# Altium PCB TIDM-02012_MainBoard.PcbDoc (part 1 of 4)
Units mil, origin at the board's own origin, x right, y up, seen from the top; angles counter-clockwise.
Board outline 6550 x 5100 mil, 4 copper layers (Top Layer, Layer 1, Layer 2, Bottom Layer), stack 81.2 mil thick; 300 components, 157 nets, 916 pads, 350 vias.
Unrouted connection lines stored in the file: 93.
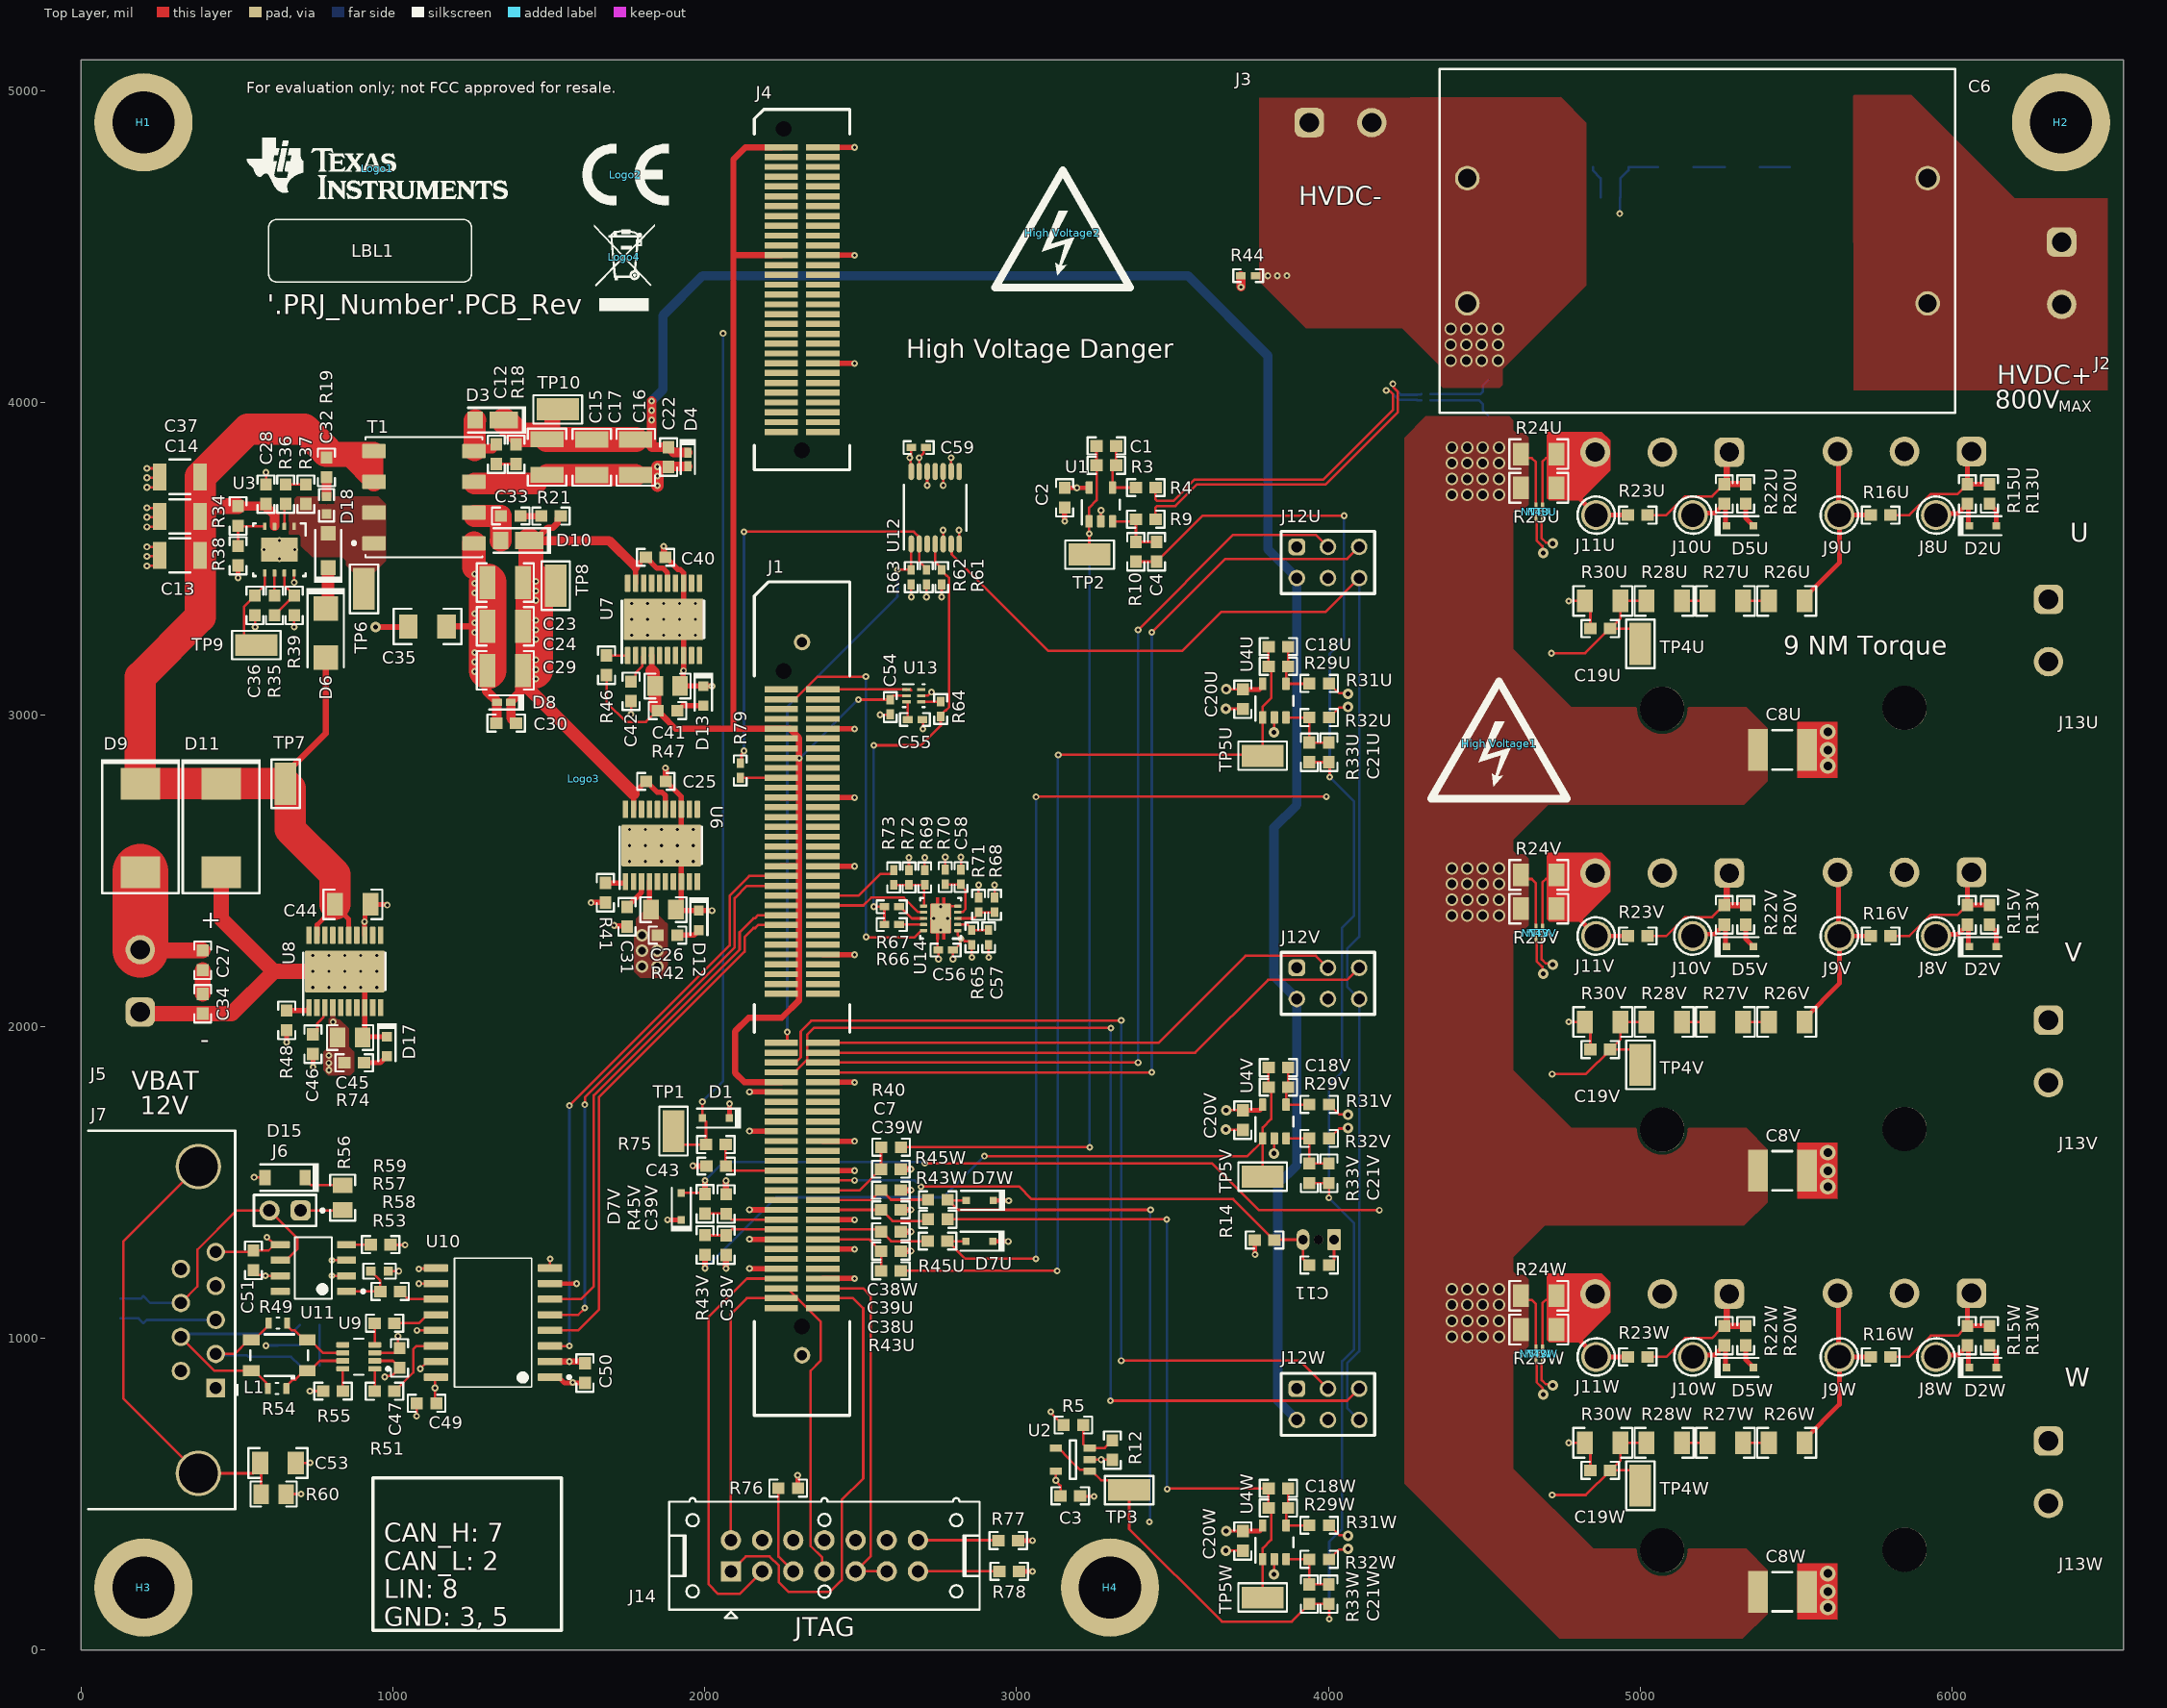
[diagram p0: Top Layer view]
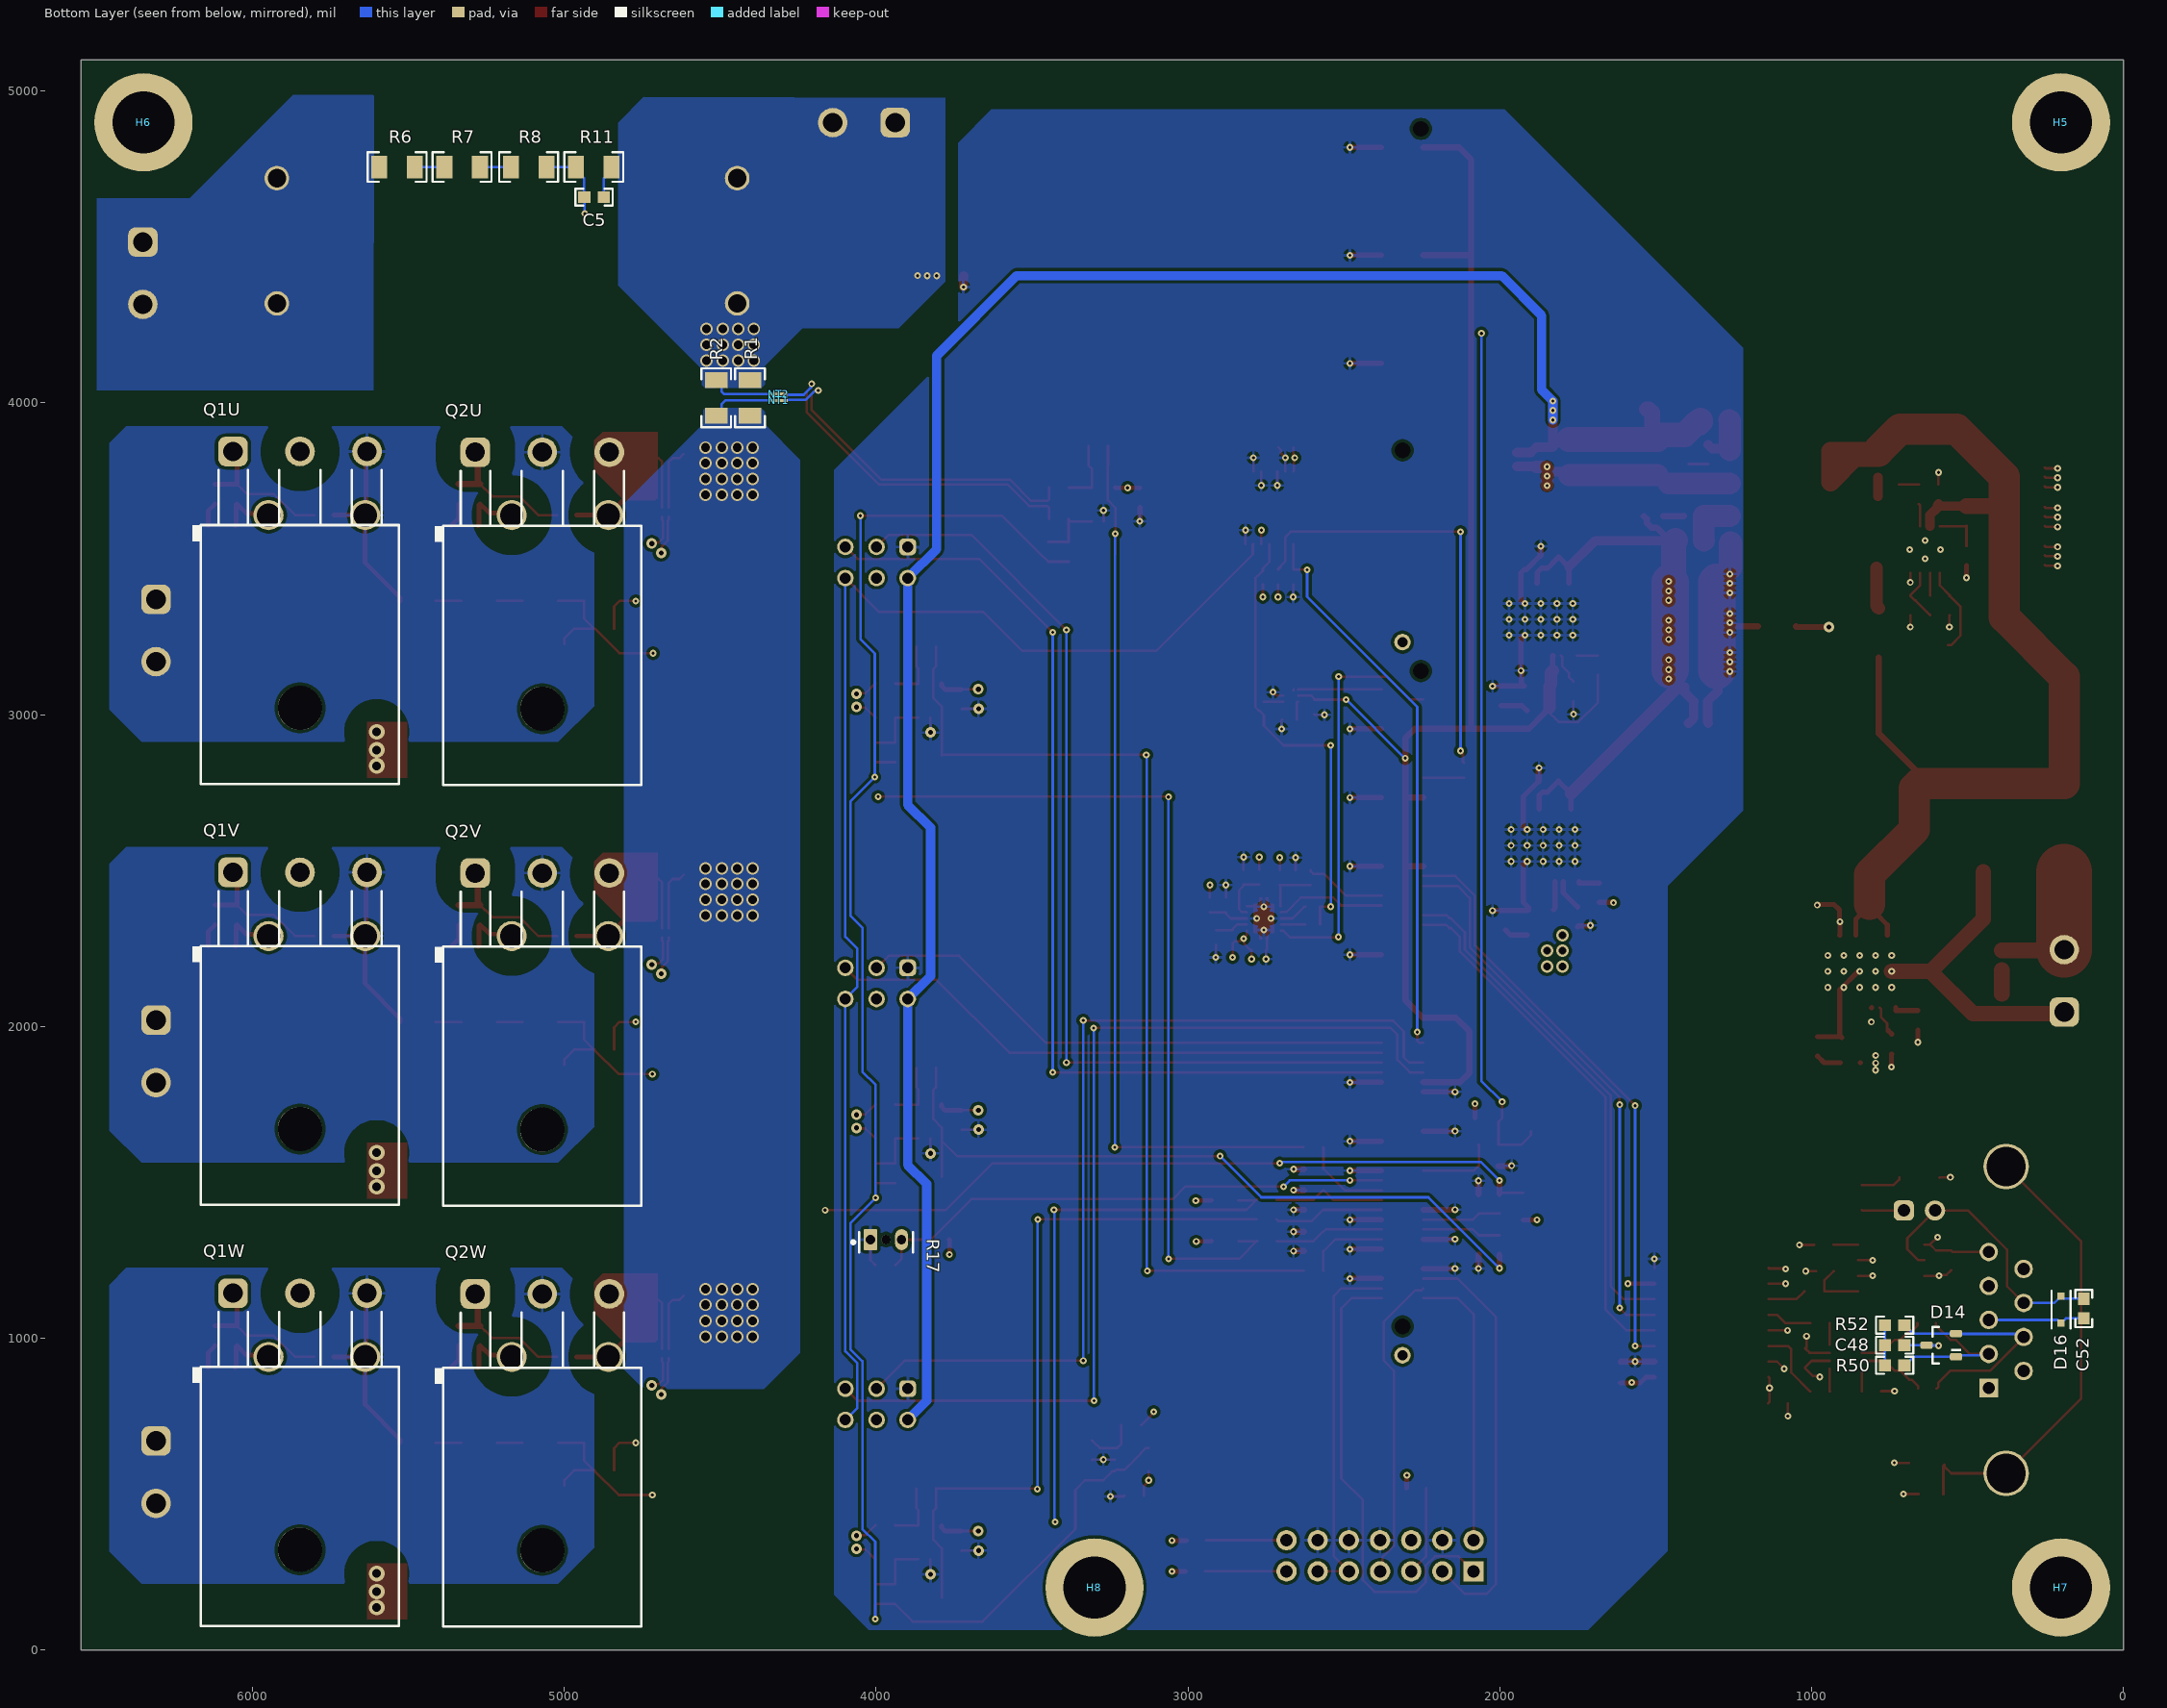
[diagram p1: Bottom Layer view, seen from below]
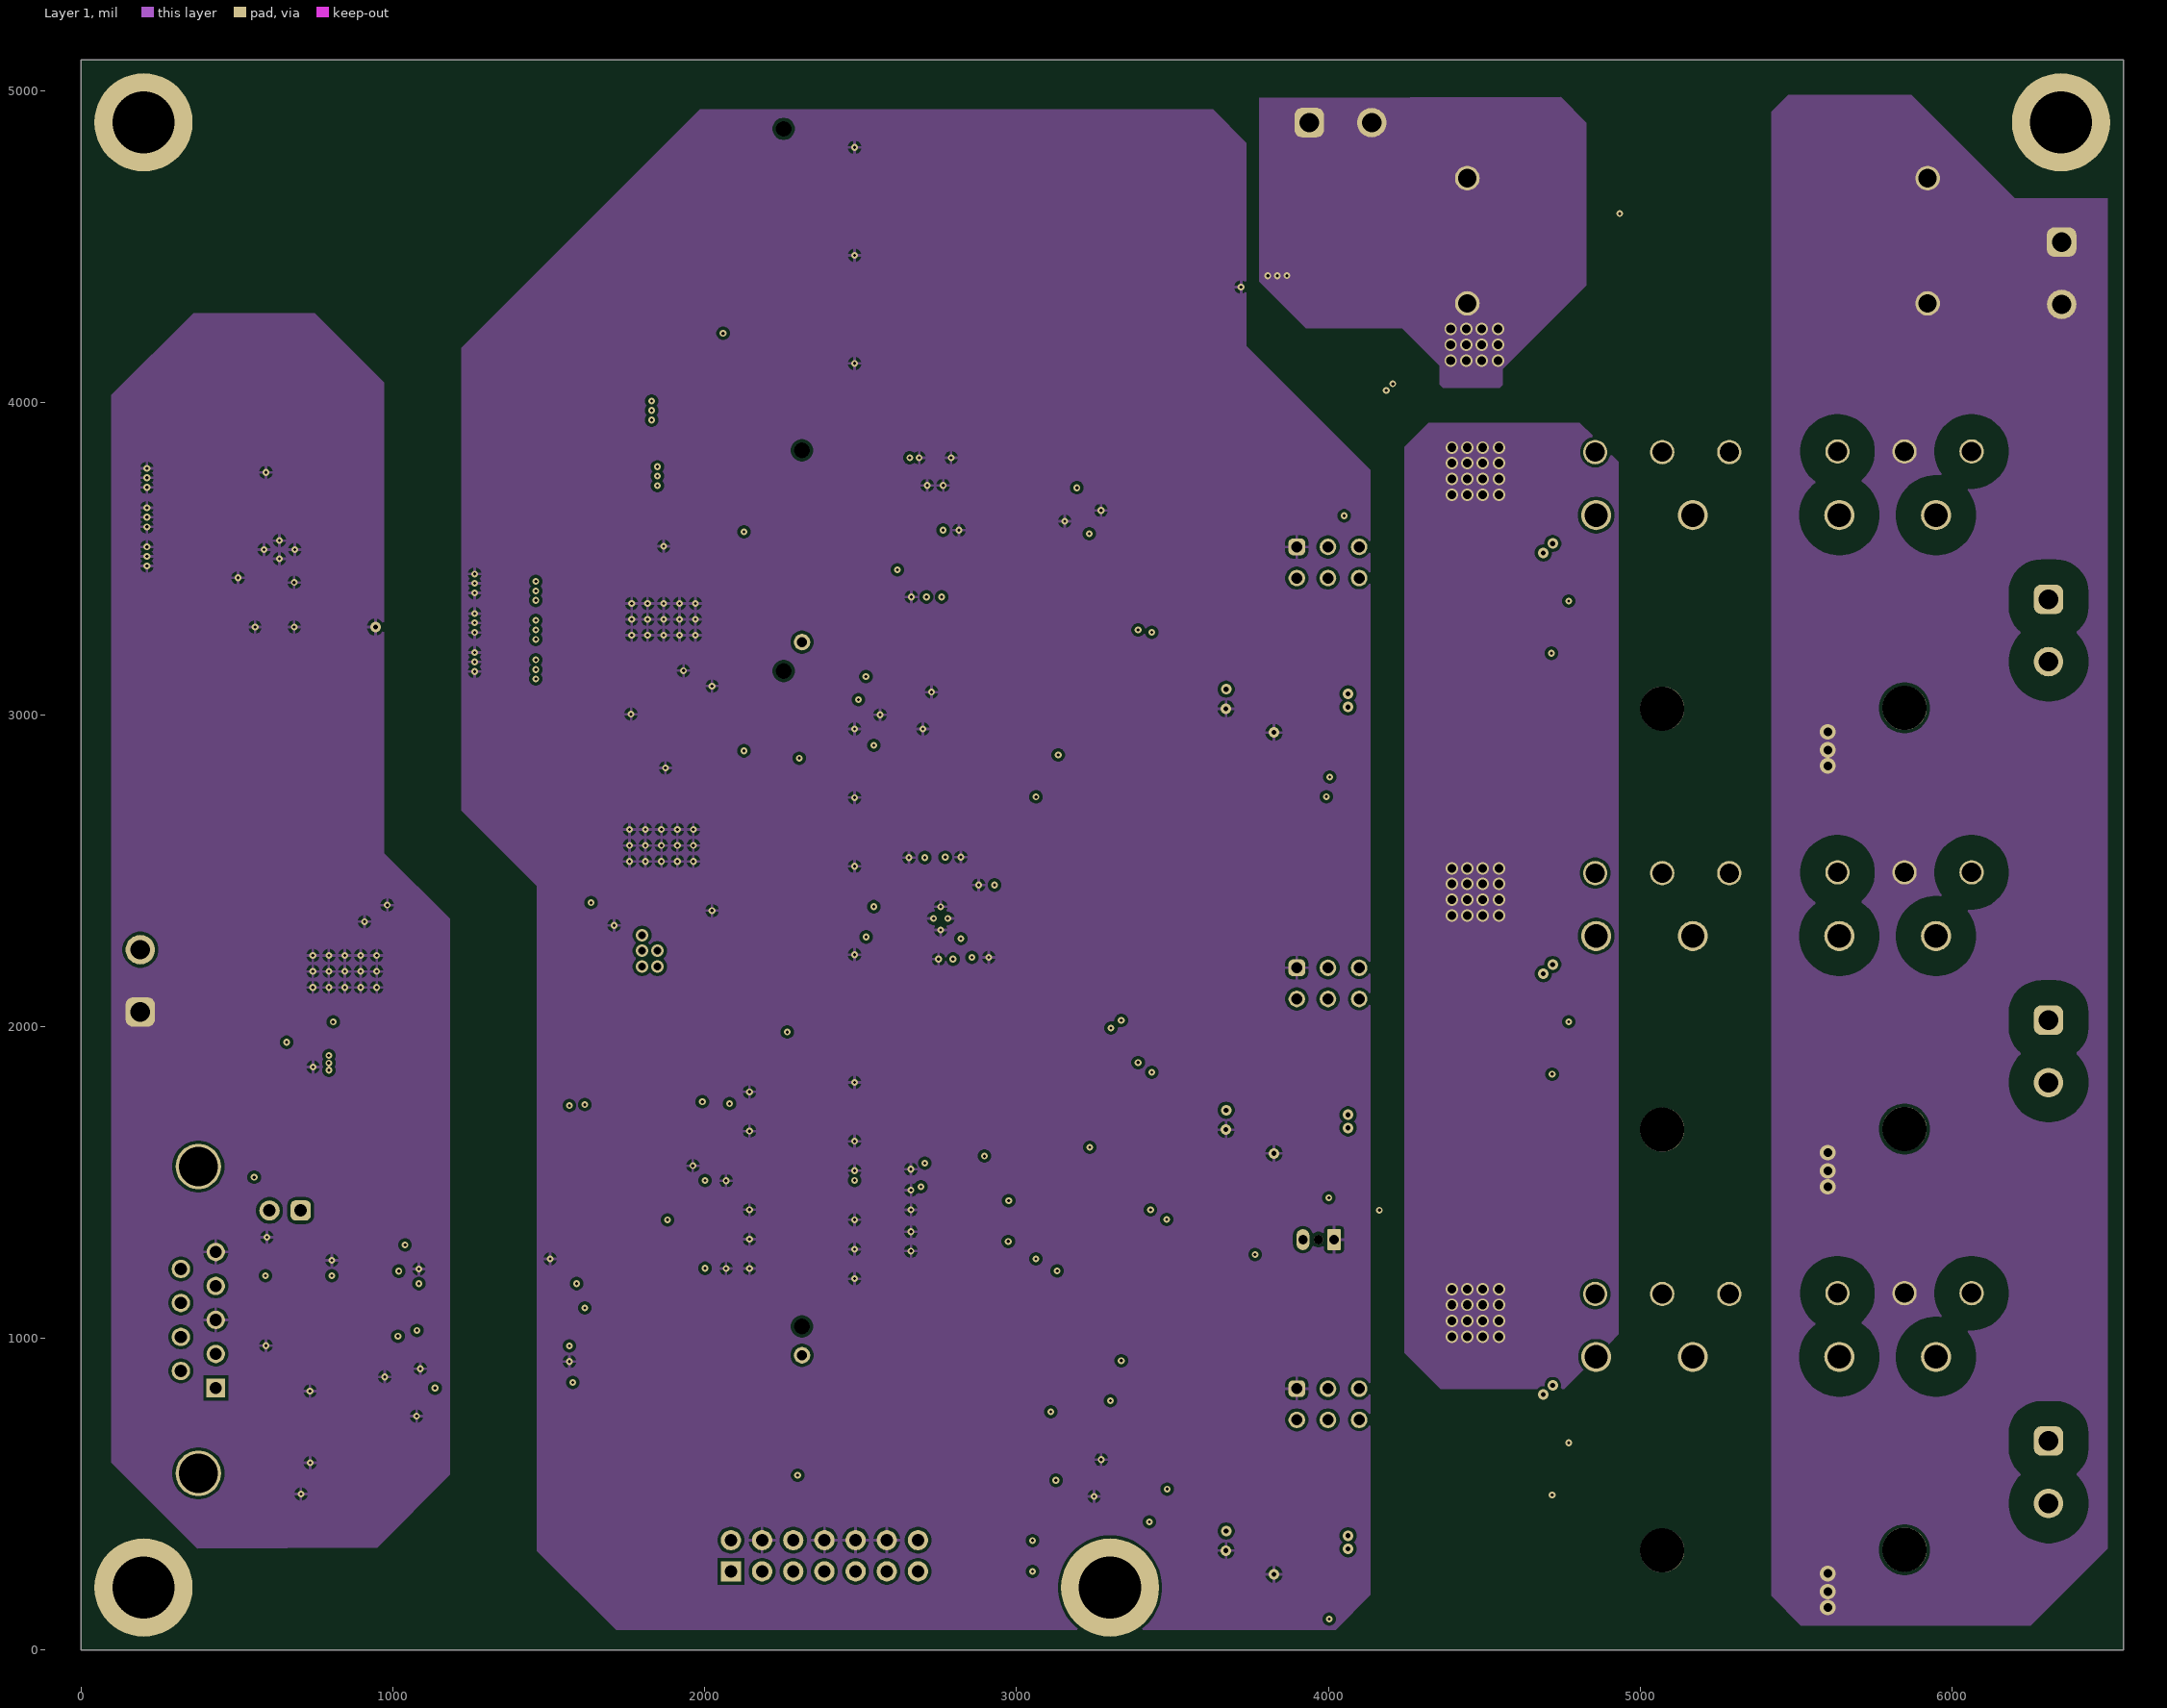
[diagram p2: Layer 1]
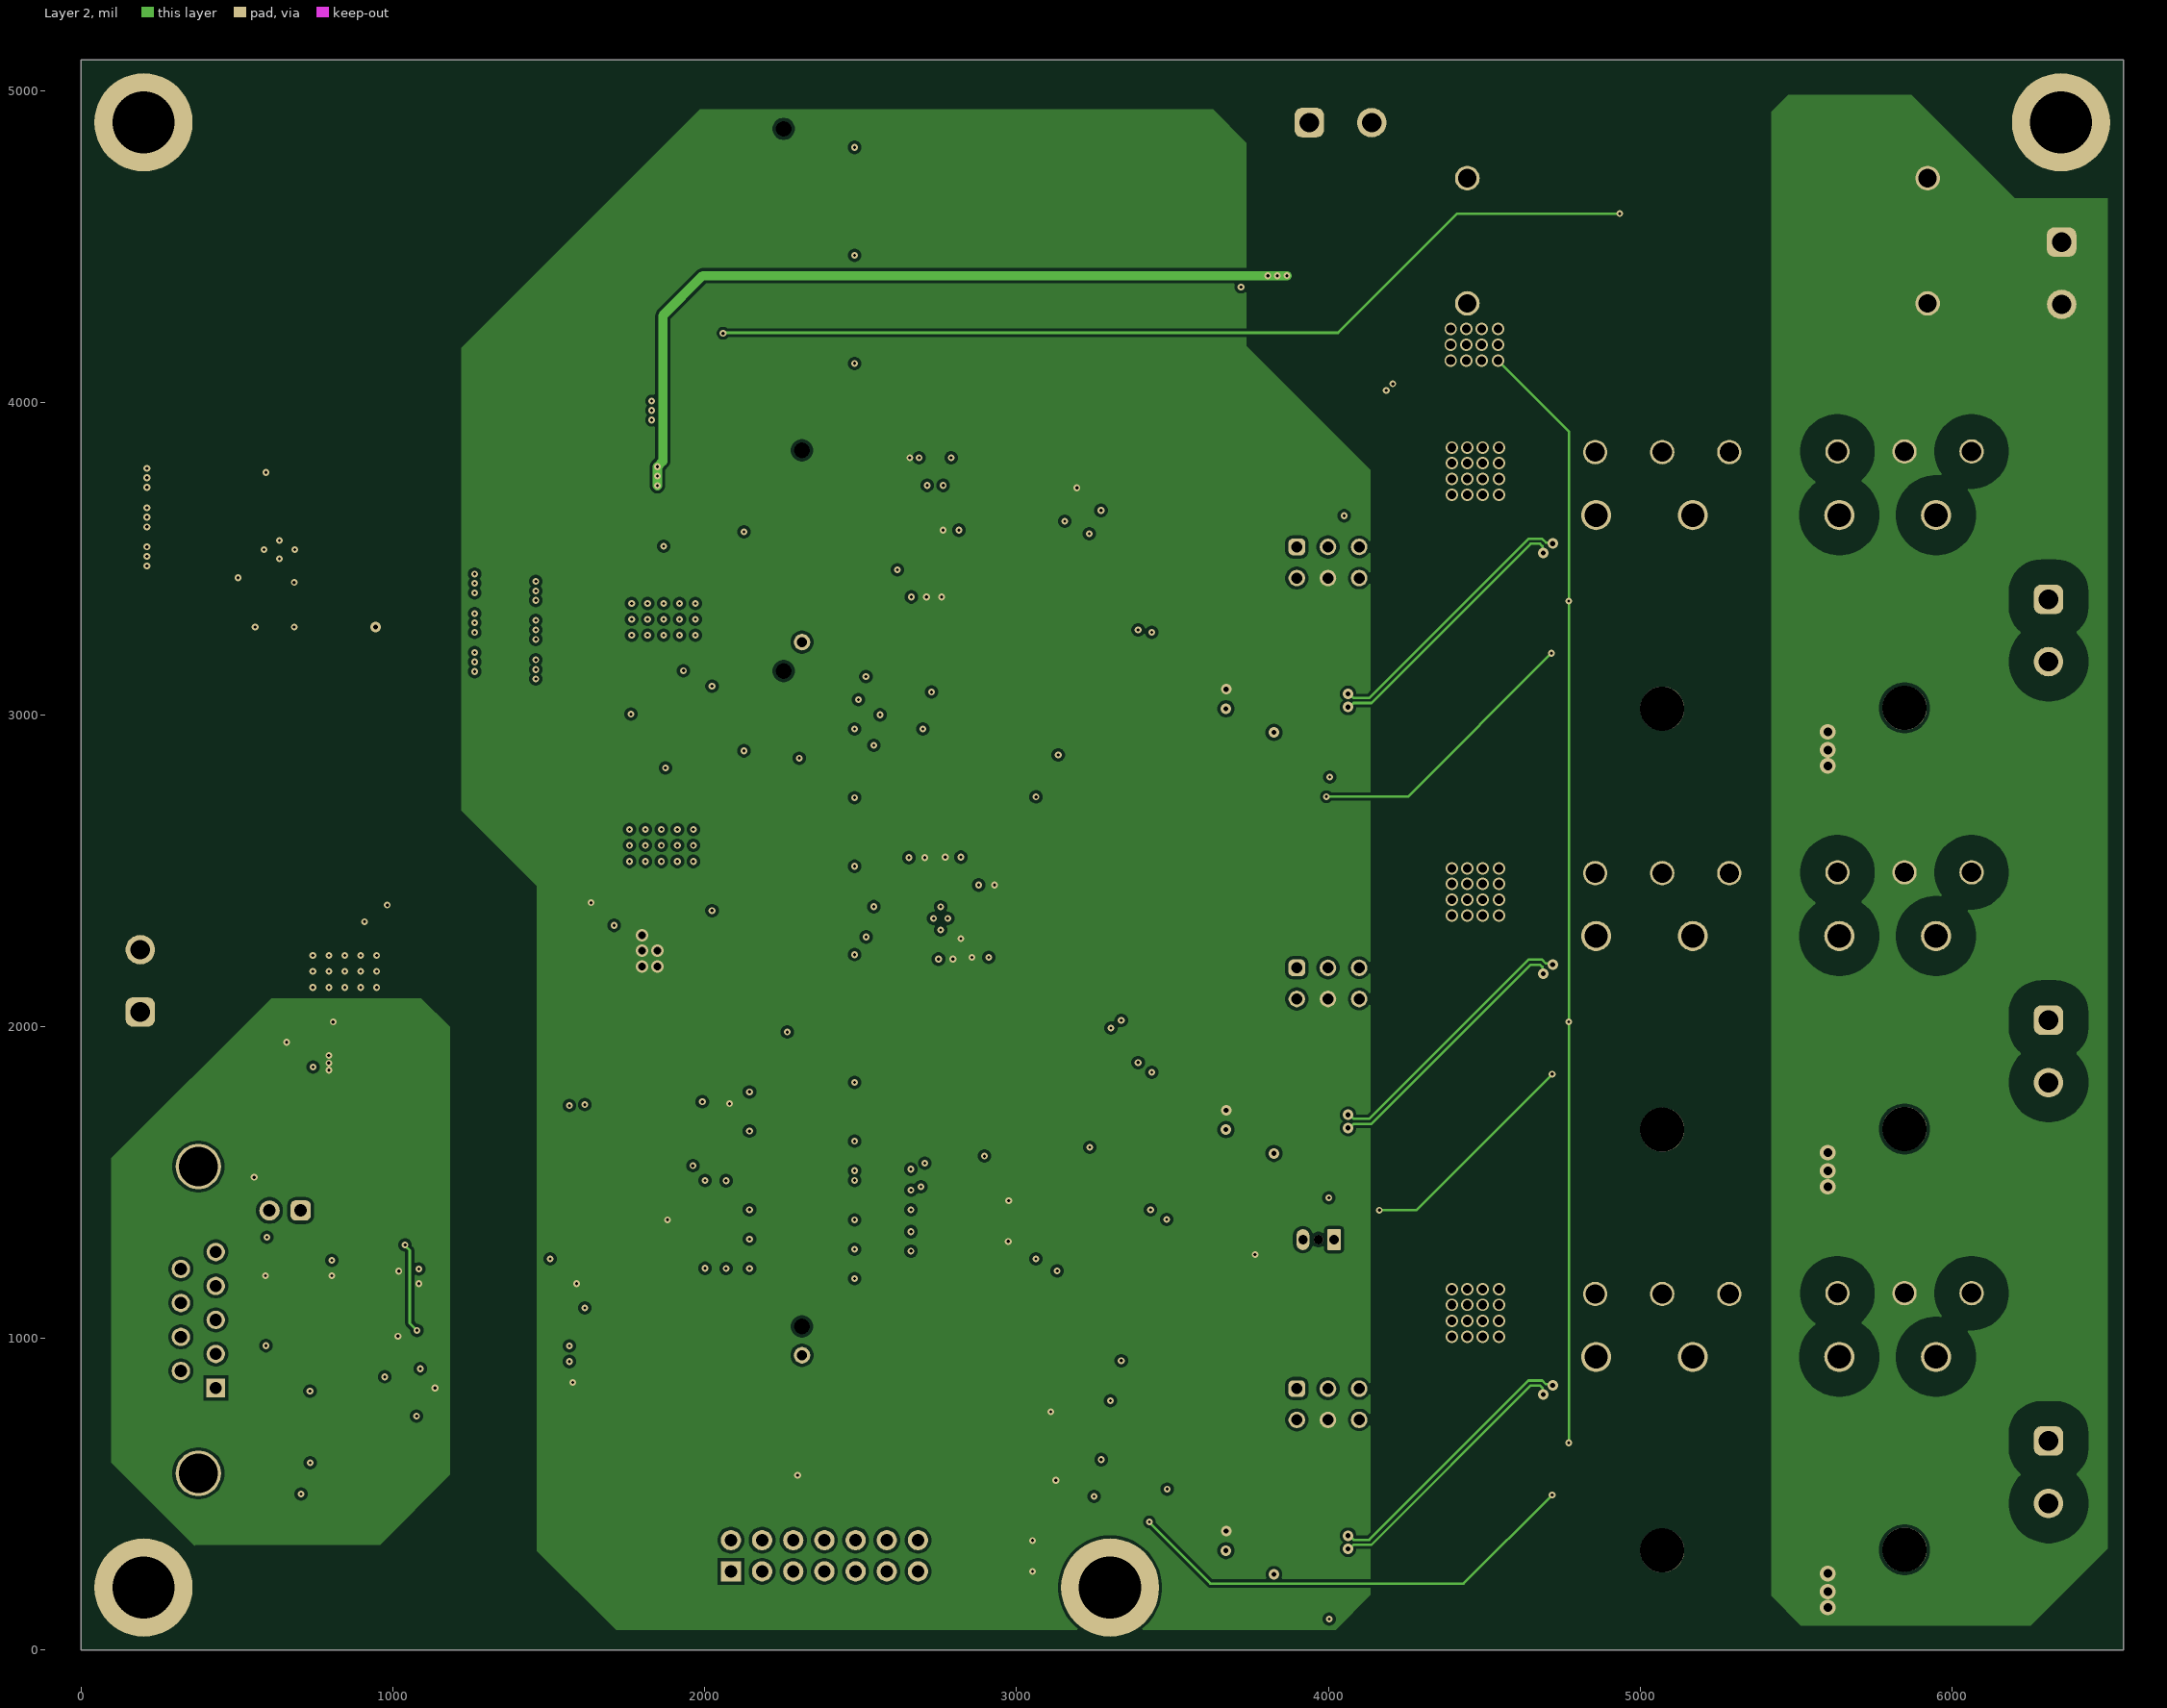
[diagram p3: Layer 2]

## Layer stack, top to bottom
Top Solder: solder mask 0.4, Solder Resist, Dk 3.5
Top Layer: signal copper 2.8
Dielectric 1: core 15, Core-009, Dk 4.5
Layer 1: signal copper 2.8
Dielectric1: core 40, FR-4 High Tg, Dk 4.8
Layer 2: signal copper 2.8
Dielectric 2: core 15, Core-009, Dk 4.5
Bottom Layer: signal copper 2.8
Bottom Solder: solder mask 0.4, Solder Resist, Dk 3.5

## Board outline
0,0 0,5100 6550,5100 6550,0

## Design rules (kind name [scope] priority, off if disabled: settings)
AcuteAngle [All] p1: minimum=4.50000000000000E+0001 checktracksonly=FALSE
AssemblyTestPointUsage [All] p1: valid=2
BoardOutlineClearance BoardOutlineClearance_MountingHoles [OnCopper and InComponentClass('Mounting Holes')] p1: gap=39.37 ignorepadtopadclearanceinfootprint=FALSE
BoardOutlineClearance BoardOutlineClearance_Poly [OnCopper and IsPoly] p2: gap=25 ignorepadtopadclearanceinfootprint=FALSE
BoardOutlineClearance [OnCopper and Not InComponentClass('Logo') and not InComponentClass('FiducialMark') and not InRegion(1000,500,4000,800) and not InPoly] p3: gap=40 ignorepadtopadclearanceinfootprint=FALSE
Clearance Clearance_HV_DC_BUS [InNetClass('HVDC') vs ((Not InNetClass('HVDC')) AND InAnyNet)] p1: gap=80 ignorepadtopadclearanceinfootprint=TRUE
Clearance Clearance_HV_Phase [InNetClass('HV') vs ((Not InNetClass('HV')) AND InAnyNet)] p2: gap=80 ignorepadtopadclearanceinfootprint=TRUE
Clearance Clearance_Keepouts [((IsTrack Or IsArc) And Not InPoly) And IsFree and IsKeepOut vs ((IsTrack Or IsArc) And Not InPoly) And IsFree and IsKeepOut] p3: gap=0 ignorepadtopadclearanceinfootprint=FALSE
Clearance Clearance_Poly [InPolygon] p4: gap=10 ignorepadtopadclearanceinfootprint=TRUE
Clearance Clearance_FiducialMark [IsKeepOut and InComponentClass('FiducialMark') vs IsPad and InComponentClass('FiducialMark')] p5: gap=0 ignorepadtopadclearanceinfootprint=FALSE
Clearance [All] p6: gap=8 ignorepadtopadclearanceinfootprint=TRUE
ComponentClearance ComponentClearance_MountingHoles_FiducialMarks [InComponentClass('Mounting Holes') vs InComponentClass('FiducialMark')] p1: gap=50 collisioncheckmode=3 verticalgap=10 showdistances=FALSE
ComponentClearance ComponentClearance_Shunt [InComponentClass('Header') vs InComponentClass('Shunt')] p2: gap=0 collisioncheckmode=3 verticalgap=0 showdistances=FALSE
ComponentClearance ComponentClearance_Logo [InComponentClass('Logo')] p3: gap=30 collisioncheckmode=3 verticalgap=10 showdistances=FALSE
ComponentClearance ComponentClearance_ScrewToNut [(HasFootprint('NY PMS 440 0025 PH')) vs (HasFootprint('Keystone_1902C'))] p4: gap=5 collisioncheckmode=3 verticalgap=10 showdistances=FALSE
ComponentClearance ComponentClearance_MountingHoles [InComponentClass('Mounting Holes')] p5: gap=100 collisioncheckmode=3 verticalgap=100000 showdistances=FALSE
ComponentClearance ComponentClearance_SmallPassives [HasFootprint('0201*') or HasFootprint('0402*') or HasFootprint('0508') or HasFootprint('0603*') or HasFootprint('0612') or HasFootprint('0805*') or HasFootprint('0815*') or HasFootprint('0830*') or HasFootprint('1206*') or HasFootprint('1210*') or HasFootprint('1808*') or HasFootprint('1812*') or HasFootprint('1825*') or HasFootprint('2010*') or HasFootprint('2220*') or HasFootprint('2225*') or HasFootprint('2512*') or HasFootprint('2728*') or HasFootprint('3518*') vs HasFootprint('0201*') or HasFootprint('0402*') or HasFootprint('0508') or HasFootprint('0603*') or HasFootprint('0612') or HasFootprint('0805*') or HasFootprint('0815*') or HasFootprint('0830*') or HasFootprint('1206*') or HasFootprint('1210*') or HasFootprint('1808*') or HasFootprint('1812*') or HasFootprint('1825*') or HasFootprint('2010*') or HasFootprint('2220*') or HasFootprint('2225*') or HasFootprint('2512*') or HasFootprint('2728*') or HasFootprint('3518*')] p6: gap=14.96 collisioncheckmode=3 verticalgap=10 showdistances=FALSE
ComponentClearance ComponentClearance_THtoSMT [IsThruComponent vs IsSMTComponent] p7 off: gap=30 collisioncheckmode=3 verticalgap=30 showdistances=FALSE
ComponentClearance ComponentClearance_THtoTH [IsThruComponent vs IsThruComponent] p8 off: gap=10 collisioncheckmode=3 verticalgap=30 showdistances=FALSE
ComponentClearance [All] p9: gap=10 collisioncheckmode=3 verticalgap=10 showdistances=FALSE
DiffPairsRouting [All] p1: maxlimit=100 minlimit=6 mostfreqgap=8 toplayer_minwidth=6 toplayer_maxwidth=15 toplayer_prefwidth=8 midlayer1_minwidth=6 midlayer1_maxwidth=15 midlayer1_prefwidth=8 midlayer2_minwidth=6 midlayer2_maxwidth=15 midlayer2_prefwidth=8 bottomlayer_minwidth=6 bottomlayer_maxwidth=15 bottomlayer_prefwidth=8 maxuncoupledlength=1000
FabricationTestPointUsage TestPointUsage [All] p1: valid=2 allowmultiple=FALSE
FabricationTestpoint Testpoint [All] p1: side=3 testpointundercomponent=TRUE minsize=40 maxsize=100 preferedsize=60 minholesize=0 maxholesize=40 preferedholesize=32 testpointgrid=1 allowsidetop=TRUE allowsidebottom=TRUE usegrid=TRUE gridtolerance=0.01
FanoutControl Fanout_LCC [IsLCC] p1: bgadir=Out bgaviamode=Centered fanoutstyle=Auto fanoutdirection=Alternating viagrid=1 // Fanout_LCC (Default Rule)
FanoutControl Fanout_BGA [IsBGA] p2: bgadir=Out bgaviamode=Centered fanoutstyle=Auto fanoutdirection=Alternating viagrid=1 // Fanout_BGA (Default Rule)
FanoutControl Fanout_Default [All] p4: bgadir=Out bgaviamode=Centered fanoutstyle=Auto fanoutdirection=Alternating viagrid=1 // Fanout_Default (Default Rule)
FanoutControl Fanout_Small [(CompPinCount < 5)] p5: bgadir=Out bgaviamode=Centered fanoutstyle=Auto fanoutdirection=OutThenIn viagrid=1 // Fanout_Small (Default Rule)
Height [All] p1: minheight=0 maxheight=3000 prefheight=500
HoleSize [All] p1: absolutevalues=TRUE maxlimit=251 minlimit=7.87 maxpercent=80.000 minpercent=20.000
MinimumAnnularRing MinimumAnnularRing_ThermalPadVias [IsVia and InAnyComponent] p1: minimumring=5.91
MinimumAnnularRing [All] p2: minimumring=6
MinimumSolderMaskSliver MinimumSolderMaskSliver_Logo [InComponentClass('Logo') vs InComponentClass('Logo')] p1: minsoldermaskwidth=0.7
MinimumSolderMaskSliver [All] p2: minsoldermaskwidth=3.94
PlaneConnect [All] p1: planeconnectstyle=Relief reliefexpansion=10 reliefentries=4 reliefconductorwidth=10 reliefairgap=10
PolygonConnect PolygonConnect_Power [(HasFootprint('TO-247') OR HasFootprint('Wurth_691311500102') OR HasFootprint('B32776_4200x2800x3700') OR InNet('DC-U') OR InNet('VBUS') OR InNet('PGND') OR InNet('VCC5_LV') OR InNet('VCC33') OR InNet('NetC32_2'))] p1: connectstyle=Direct reliefconductorwidth=10 reliefentries=4 polygonreliefangle="90 Angle" airgapwidth=10
PolygonConnect [All] p2: connectstyle=Relief reliefconductorwidth=10 reliefentries=4 polygonreliefangle="90 Angle" airgapwidth=10
RoomDefinition U [InComponentClass('U')] p1 off: confinementstyle=ConfineIn formatcopy=TRUE lockcomponents=FALSE outline 3670,2770 6500,2770 6500,4050 3670,4050
RoomDefinition W [InComponentClass('W')] p2 off: confinementstyle=ConfineIn formatcopy=TRUE lockcomponents=FALSE outline 3670,70 6500,70 6500,1350 3670,1350
RoomDefinition V [InComponentClass('V')] p3 off: confinementstyle=ConfineIn formatcopy=TRUE lockcomponents=FALSE outline 3670,1420 6500,1420 6500,2700 3670,2700
RoutingVias ThermalPadVias [IsVia and InAnyComponent] p1: holewidth=7.87 width=19.68 viastyle="Through Hole" minholewidth=7.87 minwidth=19.68 maxholewidth=12.99 maxwidth=23.62
RoutingVias [All] p2: holewidth=16 width=34 viastyle="Through Hole" minholewidth=7.87 minwidth=20 maxholewidth=40 maxwidth=65
SilkToBoardRegionClearance [Not ((IsComment or IsDesignator) And (Hide <> 'False')) and not InRegion(1000,500,4000,800)] p1:
SilkToSilkClearance SilkToSilkClearance_Pb-FreeLogo [(HasFootprint('Pb-Free_Overlay_Medium') OR HasFootprint('Pb-Free_Overlay_Small')) vs (HasFootprint('Pb-Free_Overlay_Medium') OR HasFootprint('Pb-Free_Overlay_Small'))] p1: silktosilkclearance=0
SilkToSilkClearance [All] p2: silktosilkclearance=3.94
SilkToSolderMaskClearance SilkToComponentPadClearance [(IsPad or IsFill or IsRegion) and InAnycomponent vs Not HasFootprint('TO-247_Horizontal_Down')] p1: minsilkscreentomaskgap=3 clearancetoexposedcopper=TRUE
SilkToSolderMaskClearance "Silk to Solder Mask Opening" [Not HasFootprint('Mill-Max_0312-0-15-15-34-27-10-0')] p2: minsilkscreentomaskgap=3.94 clearancetoexposedcopper=FALSE
SolderMaskExpansion [All] p1: expansion=1.97 istentingtop=FALSE
Width [All] p1: maxlimit=300 minlimit=6 preferedwidth=10 checkconnectedcopper=TRUE
14 further rules are at their usual default settings.

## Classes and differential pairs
channel class TIDM-02012_Half_Bridge: U V W
net class HV: G_1U G_1V G_1W NetD2U_2 NetD2V_2 NetD2W_2 NetQ1U_1 NetQ1V_1 NetQ1W_1 S_1U S_1V S_1W
net class HVDC: VBUS
component class W: C8W C18W C19W C20W C21W C38W C39W D2W D5W D7W J8W J9W J10W J11W J12W J13W NT3W NT4W Q1W Q2W R13W R15W R16W R20W R22W R23W R24W R25W R26W R27W R28W R29W R30W R31W R32W R33W R43W R45W TP4W TP5W U4W
component class V: C8V C18V C19V C20V C21V C38V C39V D2V D5V D7V J8V J9V J10V J11V J12V J13V NT3V NT4V Q1V Q2V R13V R15V R16V R20V R22V R23V R24V R25V R26V R27V R28V R29V R30V R31V R32V R33V R43V R45V TP4V TP5V U4V
component class U: C8U C18U C19U C20U C21U C38U C39U D2U D5U D7U J8U J9U J10U J11U J12U J13U NT3U NT4U Q1U Q2U R13U R15U R16U R20U R22U R23U R24U R25U R26U R27U R28U R29U R30U R31U R32U R33U R43U R45U TP4U TP5U U4U
component class TIDM-eCompressor_BlankSheet: C1 C2 C3 C4 C5 C6 C7 C11 C43 C54 C55 C56 C57 C58 C59 D1 J1 J2 J3 J4 J14 NT1 NT2 R1 R2 R3 R4 R5 R6 R7 R8 R9 R10 R11 R12 R14 R17 R40 R44 R61 R62 R63 R64 R65 R66 R67 R68 R69 R70 R71 R72 R73 R75 R76 R77 R78 R79 TP1 TP2 TP3 U1 U2 U12 U13 U14
component class PowerSupply: C12 C13 C14 C15 C16 C17 C22 C23 C24 C25 C26 C27 C28 C29 C30 C31 C32 C33 C34 C35 C36 C37 C40 C41 C42 C44 C45 C46 D3 D4 D6 D8 D9 D10 D11 D12 D13 D17 D18 J5 R18 R19 R21 R34 R35 R36 R37 R38 R39 R41 R42 R46 R47 R48 R74 T1 TP6 TP7 TP8 TP9 TP10 U3 U6 U7 U8
component class Header: J6
component class Comm: C47 C48 C49 C50 C51 C52 C53 D14 D15 D16 J6 J7 L1 R49 R50 R51 R52 R53 R54 R55 R56 R57 R58 R59 R60 U9 U10 U11
component class "Mounting Holes": H1 H2 H3 H4
component class Logo: Logo1
component class Hardware: H1 H2 H3 H4 H5 H6 H7 H8 "High Voltage1" "High Voltage2" LBL1 Logo1 Logo2 Logo3 Logo4 ZZ1 ZZ2 ZZ3 ZZ4
component class AssemblyNote: ZZ1 ZZ2 ZZ3 ZZ4
component class Label: LBL1
differential pair ShuntW: +ShuntW_P -ShuntW_N
differential pair ShuntV: +ShuntV_P -ShuntV_N
differential pair Shunt: +Shunt_P -Shunt_N
differential pair ShuntU: +ShuntU_P -ShuntU_N

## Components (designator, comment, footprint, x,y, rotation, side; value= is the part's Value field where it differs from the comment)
C1 "C0603C470J1GACAUTO" 0603 3287.95,3861.9 r0 top value=47pF
C2 "C0603C104K5RACTU" 0603 3154.44,3695.73 r90 top value=0.1uF
C3 "C0603C104K5RACTU" 0603 3172.63,494.37 r180 top value=0.1uF
C4 "C0603C470J1GACAUTO" 0603 3448.95,3522.4 r270 top value=47pF
C5 "06035C473JAT2A" 0603 4905,4660 r180 bottom value=0.047uF
C6 "B32776G1106K" B32776_4200x2800x3700 5184,4520 r0 top value=10uF
C7 "GRM1885C1H471JA01D" 0603 2597,1542 r0 top value=470pF
C8U "C1812V473KDRACTU" 1812 5456.17,2886.77 r180 top value=0.047uF (schematic designator C8)
C8V "C1812V473KDRACTU" 1812 5456.17,1536.77 r180 top value=0.047uF (schematic designator C8)
C8W "C1812V473KDRACTU" 1812 5456.17,186.77 r180 top value=0.047uF (schematic designator C8)
C11 "C0603C104K5RACTU" 0603 3970.5,1234.48 r180 top value=0.1uF
C12 "GRM1885C2A220JA01D" 0603 1331.69,3835.25 r90 top value=22pF
C13 "CGA6P3X7S1H106K250AB" 1210_280 316.99,3510.85 r0 top value=10uF
C14 "CGA6P3X7S1H106K250AB" 1210_280 316.99,3636.05 r0 top value=10uF
C15 "TMK325B7226KMHP" 1210_270 1494.11,3825.73 r270 top value=22uF
C16 "TMK325B7226KMHP" 1210_270 1778.6,3825.41 r270 top value=22uF
C17 "TMK325B7226KMHP" 1210_270 1637.6,3825.41 r270 top value=22uF
C18U "C0603C470J1GACAUTO" 0603 3840,3217.95 r0 top value=47pF (schematic designator C18)
C18V "C0603C470J1GACAUTO" 0603 3840,1867.95 r0 top value=47pF (schematic designator C18)
C18W "C0603C470J1GACAUTO" 0603 3840,517.95 r0 top value=47pF (schematic designator C18)
C19U "06035C473JAT2A" 0603 4872.15,3275.94 r180 top value=0.047uF (schematic designator C19)
C19V "06035C473JAT2A" 0603 4872.15,1925.94 r180 top value=0.047uF (schematic designator C19)
C19W "06035C473JAT2A" 0603 4872.15,575.94 r180 top value=0.047uF (schematic designator C19)
C20U "C0603C104K5RACTU" 0603 3726,3049.45 r90 top value=0.1uF (schematic designator C20)
C20V "C0603C104K5RACTU" 0603 3726,1699.45 r90 top value=0.1uF (schematic designator C20)
C20W "C0603C104K5RACTU" 0603 3726,349.45 r90 top value=0.1uF (schematic designator C20)
C21U "C0603C470J1GACAUTO" 0603 4001.99,2879 r270 top value=47pF (schematic designator C21)
C21V "C0603C470J1GACAUTO" 0603 4001.99,1529 r270 top value=47pF (schematic designator C21)
C21W "C0603C470J1GACAUTO" 0603 4001.99,179 r270 top value=47pF (schematic designator C21)
C22 "C0603C104K5RACAUTO" 0603 1884.1,3826.47 r270 top value=0.1uF
C23 "TMK325B7226KMHP" 1210_270 1360.37,3423.95 r0 top value=22uF
C24 "TMK325B7226KMHP" 1210_270 1360.37,3282.95 r0 top value=22uF
C25 "CGA3E1X7R1E105M080AC" 0603 1843.44,2785.92 r0 top value=1uF
C26 "EMK212BB7106MG-T" 0805_HV 1867.5,2374.34 r0 top value=10uF
C27 "CGA3E2X7R1H473K080AA" 0603 389.97,2212.29 r270 top value=0.047uF
C28 "C0603C104K5RACTU" 0603 592.96,3707.03 r90 top value=0.1uF
C29 "TMK325B7226KMHP" 1210_270 1360.37,3141.95 r0 top value=22uF
C30 "C0603C104K5RACAUTO" 0603 1363.18,2972.87 r0 top value=0.1uF
C31 "C0603C104K5RACTU" 0603 1750.73,2351.51 r270 top value=0.1uF
C32 "GRM1885C2A220JA01D" 0603_HV 786.82,3671.36 r270 top value=22pF
C33 "GRM1885C2A220JA01D" 0603 1377.99,3637.4 r180 top value=22pF
C34 "CGA3E2X7R1H473K080AA" 0603 389.97,2072.5 r270 top value=0.047uF
C35 "202R18W102KV4E" 1206_190M 1110.83,3282.95 r180 top value=1000pF
C36 "GCM188R71E473KA37D" 0603 557.34,3350.54 r270 top value=0.047uF
C37 "CGA6P3X7S1H106K250AB" 1210_280 316.99,3762.74 r0 top value=10uF
C38U "GRM1885C1H471JA01D" 0603 2597.2,1279.51 r0 top value=470pF (schematic designator C38)
C38V "GRM1885C1H471JA01D" 0603 2068.3,1298.46 r270 top value=470pF (schematic designator C38)
C38W "GRM1885C1H471JA01D" 0603 2597.2,1411.65 r0 top value=470pF (schematic designator C38)
C39U "GRM1885C1H221JA01D" 0603 2597.2,1341.5 r0 top value=220pF (schematic designator C39)
C39V "GRM1885C1H221JA01D" 0603 2068.3,1430 r90 top value=220pF (schematic designator C39)
C39W "GRM1885C1H221JA01D" 0603 2597.2,1474.65 r0 top value=220pF (schematic designator C39)
C40 "CGA3E1X7R1E105M080AC" 0603 1842.54,3504.69 r0 top value=1uF
C41 "EMK212BB7106MG-T" 0805_HV 1881.04,3091.69 r0 top value=10uF
C42 "C0603C104K5RACTU" 0603 1763.61,3074.69 r270 top value=0.1uF
C43 "GRM1885C1H221JA01D" 0603 2036.8,1552 r180 top value=220pF
C44 "GMK316AB7106KL" 1206 871.3,2391.27 r0 top value=10uF
C45 "EMK212BB7106MG-T" 0805_HV 862.62,1964.27 r0 top value=10uF
C46 "C0603C104K5RACTU" 0603 743.26,1943.2 r270 top value=0.1uF
C47 "C0603C104J4RACTU" 0603 1021,936.5 r270 top value=0.1uF
C48 "CGA3E2X7R2A472K080AA" 0603 733.5,977.6 r0 bottom value=4700pF
C49 "C0603C104J4RACTU" 0603 1108,791 r180 top value=0.1uF
C50 "C0603C104J4RACTU" 0603 1616,888 r90 top value=0.1uF
C51 "C0603C104J4RACTU" 0603 552.75,1249.8 r90 top value=0.1uF
C52 "06035A221JAT2A" 0603 127.08,1095.08 r270 bottom value=220pF
C53 "12061C103JAT2A" 1206 631.36,599.5 r0 top value=0.01uF
C54 "GCM155R71C104JA55D" 0402 2595,3024.38 r270 top value=0.1uF
C55 "GCM155R71C104JA55D" 0402 2674.4,2984.32 r0 top value=0.1uF
C56 "GCM155R71C104JA55D" 0402 2772.56,2244.84 r180 top value=0.1uF
C57 "GCM155R71C104JA55D" 0402 2910.58,2285.44 r270 top value=0.1uF
C58 "GCM155R71C104JA55D" 0402 2821.77,2479.08 r90 top value=0.1uF
C59 "CGA2B3X7R1E104K050BB" 0402 2686.04,3856.61 r0 top value=0.1uF
D1 "ZLLS400QTA" SOD-323 2035.69,1706 r180 top value=40V
D2U "CUS05S40,H3F" SOD-323 6099.14,3605.95 r0 top value=40V (schematic designator D2)
D2V "CUS05S40,H3F" SOD-323 6099.14,2255.95 r0 top value=40V (schematic designator D2)
D2W "CUS05S40,H3F" SOD-323 6099.14,905.95 r0 top value=40V (schematic designator D2)
D3 "FSV360FP" SOD-123HE 1320.41,3944.93 r180 top value=60V
D4 "BZT52C18T-7" SOD-523 1946,3818.65 r270 top value=18V
D5U "CUS05S40,H3F" SOD-323 5320.14,3605.95 r0 top value=40V (schematic designator D5)
D5V "CUS05S40,H3F" SOD-323 5320.14,2255.95 r0 top value=40V (schematic designator D5)
D5W "CUS05S40,H3F" SOD-323 5320.14,905.95 r0 top value=40V (schematic designator D5)
D6 "3SMAJ5935B-TP" SMA 784.49,3262 r270 top value=27V
D7U "ZLLS400QTA" SOD-323 2881,1310.79 r180 top value=40V (schematic designator D7)
D7V "ZLLS400QTA" SOD-323 1925.13,1422.49 r90 top value=40V (schematic designator D7)
D7W "ZLLS400QTA" SOD-323 2882,1442 r180 top value=40V (schematic designator D7)
D8 "BZT52C8V2T-7" SOD-523 1355.84,3039.36 r180 top value=8.2V
D9 "SS3H10HE3_A/I" SMC_265 190,2636.61 r270 top value=100V
D10 "FSV360FP" SOD-123HE 1401.6,3558.27 r180 top value=60V
D11 "TPSMD26A" SMC_265 448.97,2636.61 r270 top value=26V
D12 "150060YS75000" WL-SMCW_YELLOW 1981.14,2340.06 r270 top value=Yellow
D13 "150060YS75000" WL-SMCW_YELLOW 1995.9,3060.19 r270 top value=Yellow
D14 "NUP2105LT1G" SOT-23 584.24,977.6 r0 bottom value=24V
D15 "1N4148W-TP" SOD-123 654.27,1514.96 r180 top value=100V
D16 "PESD1LIN,115" SOD-323-Bi 200,1091.52 r90 bottom value=15V
D17 "150060YS75000" WL-SMCW_YELLOW 980.73,1935.72 r270 top value=Yellow
D18 "PMEG60T30ELRX" SOD-123W 792.3,3526.44 r90 top value=60V
H1 "NY PMS 440 0025 PH" "NY PMS 440 0025 PH" 200,4900 r0 top locked
H2 "NY PMS 440 0025 PH" "NY PMS 440 0025 PH" 6350,4900 r0 top locked
H3 "NY PMS 440 0025 PH" "NY PMS 440 0025 PH" 200,200 r0 top locked
H4 "NY PMS 440 0025 PH" "NY PMS 440 0025 PH" 3300,200 r0 top locked
H5 "1902C" Keystone_1902C 200,4900 r180 bottom locked
H6 "1902C" Keystone_1902C 6350,4900 r180 bottom locked
H7 "1902C" Keystone_1902C 200,200 r180 bottom locked
H8 "1902C" Keystone_1902C 3300,200 r180 bottom locked
"High Voltage1" "DANGER HIGH VOLTAGE" IEC_HighVoltage_Medium 4547.5,2906.45 r0 top
"High Voltage2" "DANGER HIGH VOLTAGE" IEC_HighVoltage_Medium 3148,4545 r0 top
J1 "HSEC8-160-01-L-DV-A-BL" controlCARD-120HSEC 2312.94,2016.26 r90 top locked
J2 "691311500102" Wurth_691311500102 6352,4416 r270 top
J3 "691311500102" Wurth_691311500102 4039,4899 r0 top
J4 "HSEC8-130-01-L-DV-A" controlCARD-180HSEC-60pinAddon 2312.07,4363.34 r90 top locked
J5 "691311500102" Wurth_691311500102 190,2146.15 r90 top
J6 "TSW-102-07-G-S" TSW-102-07-G-S 654.27,1409.45 r180 top
J7 "618009231121" Wurth_618009231121 1.89,1058.47 r180 top
J8U "0312-0-15-15-34-27-10-0" Mill-Max_0312-0-15-15-34-27-10-0 5949,3640 r0 top (schematic designator J8)
J8V "0312-0-15-15-34-27-10-0" Mill-Max_0312-0-15-15-34-27-10-0 5949,2290 r0 top (schematic designator J8)
J8W "0312-0-15-15-34-27-10-0" Mill-Max_0312-0-15-15-34-27-10-0 5949,940 r0 top (schematic designator J8)
J9U "0312-0-15-15-34-27-10-0" Mill-Max_0312-0-15-15-34-27-10-0 5639,3640 r0 top (schematic designator J9)
J9V "0312-0-15-15-34-27-10-0" Mill-Max_0312-0-15-15-34-27-10-0 5639,2290 r0 top (schematic designator J9)
J9W "0312-0-15-15-34-27-10-0" Mill-Max_0312-0-15-15-34-27-10-0 5639,940 r0 top (schematic designator J9)
J10U "0312-0-15-15-34-27-10-0" Mill-Max_0312-0-15-15-34-27-10-0 5169,3640 r90 top (schematic designator J10)
J10V "0312-0-15-15-34-27-10-0" Mill-Max_0312-0-15-15-34-27-10-0 5169,2290 r90 top (schematic designator J10)
J10W "0312-0-15-15-34-27-10-0" Mill-Max_0312-0-15-15-34-27-10-0 5169,940 r90 top (schematic designator J10)
J11U "0312-0-15-15-34-27-10-0" Mill-Max_0312-0-15-15-34-27-10-0 4859,3640 r0 top (schematic designator J11)
J11V "0312-0-15-15-34-27-10-0" Mill-Max_0312-0-15-15-34-27-10-0 4859,2290 r0 top (schematic designator J11)
J11W "0312-0-15-15-34-27-10-0" Mill-Max_0312-0-15-15-34-27-10-0 4859,940 r0 top (schematic designator J11)
J12U "215307-3" TE_215307-3 3999,3488 r0 top (schematic designator J12)
J12V "215307-3" TE_215307-3 3999,2138 r0 top (schematic designator J12)
J12W "215307-3" TE_215307-3 3999,788 r0 top (schematic designator J12)
J13U "691311500102" Wurth_691311500102 6310,3270 r270 top (schematic designator J13)
J13V "691311500102" Wurth_691311500102 6310,1920 r270 top (schematic designator J13)
J13W "691311500102" Wurth_691311500102 6310,570 r270 top (schematic designator J13)
J14 "SBH11-PBPC-D07-ST-BK" CONN_SBH11-PBPC-D07-ST-BK 2384,302 r0 top
L1 "ACT45B-101-2P-TL003" ACT45B 635.57,945.21 r180 top value=100uH
LBL1 "THT-14-423-10" Label_650x200 926.74,4488 r0 top
Logo1 "Texas Instruments" TI_Stacked_Overlay_Small 950,4752 r0 top
Logo2 "CE Mark" CE_Mark_5mm 1746,4732 r0 top
Logo3 "FCC disclaimer" FCC_disclaimer 1612,2795 r0 top
Logo4 "WEEE logo" WEEE_Minimum 1741,4468.1 r0 top
NT1 "Net-Tie" Net-Tie_10milWide_30milLong 4313,4007.74 r180 bottom net-tie
NT2 "Net-Tie" Net-Tie_10milWide_30milLong 4313,4028 r180 bottom net-tie
NT3U "Net-Tie" Net-Tie_10milWide_30milLong 4687,3650 r270 top net-tie (schematic designator NT3)
NT3V "Net-Tie" Net-Tie_10milWide_30milLong 4687,2300 r270 top net-tie (schematic designator NT3)
NT3W "Net-Tie" Net-Tie_10milWide_30milLong 4687,950 r270 top net-tie (schematic designator NT3)
NT4U "Net-Tie" Net-Tie_10milWide_30milLong 4666,3650 r270 top net-tie (schematic designator NT4)
NT4V "Net-Tie" Net-Tie_10milWide_30milLong 4666,2300 r270 top net-tie (schematic designator NT4)
NT4W "Net-Tie" Net-Tie_10milWide_30milLong 4666,950 r270 top net-tie (schematic designator NT4)
Q1U "IKW25N120H3FKSA1" TO-247_Horizontal_Down 5848,3844.2 r180 bottom value="1200 V" (schematic designator Q1)
Q1V "IKW25N120H3FKSA1" TO-247_Horizontal_Down 5848,2494.2 r180 bottom value="1200 V" (schematic designator Q1)
Q1W "IKW25N120H3FKSA1" TO-247_Horizontal_Down 5848,1144.2 r180 bottom value="1200 V" (schematic designator Q1)
Q2U "IKW25N120H3FKSA1" TO-247_Horizontal_Down 5070.99,3841.83 r180 bottom value="1200 V" (schematic designator Q2)
Q2V "IKW25N120H3FKSA1" TO-247_Horizontal_Down 5070.99,2491.83 r180 bottom value="1200 V" (schematic designator Q2)
Q2W "IKW25N120H3FKSA1" TO-247_Horizontal_Down 5070.99,1141.83 r180 bottom value="1200 V" (schematic designator Q2)
R1 "WSLP1206R0100FEA" 1206 4405,4016 r270 bottom value=0.01
R2 "WSLP1206R0100FEA" 1206 4513.02,4016 r270 bottom value=0.01
R3 "RC0603FR-0710KL" 0603 3287.95,3799.9 r180 top value=10.0k
R4 "RC0603FR-071KL" 0603 3414.5,3728.21 r180 top value=1.00k
R5 "RC0603FR-0710KL" 0603 3182.47,721.37 r180 top value=10.0k
R6 "ERJ-8ENF4993V" 1206 5536.34,4756.57 r0 bottom value=499k
R7 "ERJ-8ENF4993V" 1206 5327.98,4756.57 r0 bottom value=499k
R8 "ERJ-8ENF4993V" 1206 5114.44,4756.57 r0 bottom value=499k
R9 "RC0603FR-071KL" 0603 3414.5,3626.87 r180 top value=1.00k
R10 "RC0603FR-0710KL" 0603 3382.44,3522.4 r90 top value=10.0k
R11 "ERJ-8ENF5111V" 1206 4905.47,4756.57 r0 bottom value=5.11k
R12 "RC0603FR-0710KL" 0603 3307.47,640.87 r90 top value=10.0k
R13U "CRCW06031R00FKEA" 0603 6120.33,3707.98 r90 top value=1.00 (schematic designator R13)
R13V "CRCW06031R00FKEA" 0603 6120.33,2357.98 r90 top value=1.00 (schematic designator R13)
R13W "CRCW06031R00FKEA" 0603 6120.33,1007.98 r90 top value=1.00 (schematic designator R13)
R14 "RC0603FR-0710KL" 0603 3795.5,1314.73 r180 top value=10.0k
R15U "RC0603FR-075R11L" 0603 6049.76,3707.98 r90 top value=5.11 (schematic designator R15)
R15V "RC0603FR-075R11L" 0603 6049.76,2357.98 r90 top value=5.11 (schematic designator R15)
R15W "RC0603FR-075R11L" 0603 6049.76,1007.98 r90 top value=5.11 (schematic designator R15)
R16U "RC0603FR-0710KL" 0603 5771.5,3640 r0 top value=10.0k (schematic designator R16)
R16V "RC0603FR-0710KL" 0603 5771.5,2290 r0 top value=10.0k (schematic designator R16)
R16W "RC0603FR-0710KL" 0603 5771.5,940 r0 top value=10.0k (schematic designator R16)
R17 "TMP6131QLPGMQ1" LPG0002A-MFG 3968.46,1307.84 r180 bottom value=10k
R18 "CRCW0603100RFKEAHP" 0603 1394.84,3835.25 r90 top value=100
R19 "CRCW0603100RFKEA" 0603 786.82,3793.15 r90 top value=100
R20U "CRCW06031R00FKEA" 0603 5338.84,3707.98 r90 top value=1.00 (schematic designator R20)
R20V "CRCW06031R00FKEA" 0603 5338.84,2357.98 r90 top value=1.00 (schematic designator R20)
R20W "CRCW06031R00FKEA" 0603 5338.84,1007.98 r90 top value=1.00 (schematic designator R20)
R21 "CRCW0603100RFKEAHP" 0603 1507,3636.91 r0 top value=100
R22U "RC0603FR-075R11L" 0603 5270.1,3707.98 r90 top value=5.11 (schematic designator R22)
R22V "RC0603FR-075R11L" 0603 5270.1,2357.98 r90 top value=5.11 (schematic designator R22)
R22W "RC0603FR-075R11L" 0603 5270.1,1007.98 r90 top value=5.11 (schematic designator R22)
R23U "RC0603FR-0710KL" 0603 4992.5,3640 r0 top value=10.0k (schematic designator R23)
R23V "RC0603FR-0710KL" 0603 4992.5,2290 r0 top value=10.0k (schematic designator R23)
R23W "RC0603FR-0710KL" 0603 4992.5,940 r0 top value=10.0k (schematic designator R23)
R24U "WSLP1206R0100FEA" 1206 4674.77,3835.93 r0 top value=0.01 (schematic designator R24)
R24V "WSLP1206R0100FEA" 1206 4674.77,2485.93 r0 top value=0.01 (schematic designator R24)
R24W "WSLP1206R0100FEA" 1206 4674.77,1135.93 r0 top value=0.01 (schematic designator R24)
R25U "WSLP1206R0100FEA" 1206 4674.77,3727.66 r0 top value=0.01 (schematic designator R25)
R25V "WSLP1206R0100FEA" 1206 4674.77,2377.66 r0 top value=0.01 (schematic designator R25)
R25W "WSLP1206R0100FEA" 1206 4674.77,1027.66 r0 top value=0.01 (schematic designator R25)
R26U "ERJ-8ENF4993V" 1206 5469.94,3364.52 r0 top value=499k (schematic designator R26)
R26V "ERJ-8ENF4993V" 1206 5469.94,2014.52 r0 top value=499k (schematic designator R26)
R26W "ERJ-8ENF4993V" 1206 5469.94,664.52 r0 top value=499k (schematic designator R26)
R27U "ERJ-8ENF4993V" 1206 5273.72,3364.52 r0 top value=499k (schematic designator R27)
R27V "ERJ-8ENF4993V" 1206 5273.72,2014.52 r0 top value=499k (schematic designator R27)
R27W "ERJ-8ENF4993V" 1206 5273.72,664.52 r0 top value=499k (schematic designator R27)
R28U "ERJ-8ENF4993V" 1206 5076.87,3364.52 r0 top value=499k (schematic designator R28)
R28V "ERJ-8ENF4993V" 1206 5076.87,2014.52 r0 top value=499k (schematic designator R28)
R28W "ERJ-8ENF4993V" 1206 5076.87,664.52 r0 top value=499k (schematic designator R28)
R29U "RC0603FR-0710KL" 0603 3840,3154.95 r180 top value=10.0k (schematic designator R29)
R29V "RC0603FR-0710KL" 0603 3840,1804.95 r180 top value=10.0k (schematic designator R29)
R29W "RC0603FR-0710KL" 0603 3840,454.95 r180 top value=10.0k (schematic designator R29)
R30U "ERJ-8ENF5111V" 1206 4880.02,3364.52 r0 top value=5.11k (schematic designator R30)
R30V "ERJ-8ENF5111V" 1206 4880.02,2014.52 r0 top value=5.11k (schematic designator R30)
R30W "ERJ-8ENF5111V" 1206 4880.02,664.52 r0 top value=5.11k (schematic designator R30)
R31U "RC0603FR-071KL" 0603 3970.5,3099.95 r180 top value=1.00k (schematic designator R31)
R31V "RC0603FR-071KL" 0603 3970.5,1749.95 r180 top value=1.00k (schematic designator R31)
R31W "RC0603FR-071KL" 0603 3970.5,399.95 r180 top value=1.00k (schematic designator R31)
R32U "RC0603FR-071KL" 0603 3970.5,2990.82 r180 top value=1.00k (schematic designator R32)
R32V "RC0603FR-071KL" 0603 3970.5,1640.82 r180 top value=1.00k (schematic designator R32)
R32W "RC0603FR-071KL" 0603 3970.5,290.82 r180 top value=1.00k (schematic designator R32)
R33U "RC0603FR-0710KL" 0603 3939,2879 r90 top value=10.0k (schematic designator R33)
R33V "RC0603FR-0710KL" 0603 3939,1529 r90 top value=10.0k (schematic designator R33)
R33W "RC0603FR-0710KL" 0603 3939,179 r90 top value=10.0k (schematic designator R33)
R34 "RC0603FR-0717K8L" 0603 503.34,3637.4 r90 top value=17.8k
R35 "RC0603FR-07324KL" 0603 620.22,3350.54 r90 top value=324k
R36 "RC0603FR-0761K9L" 0603 655.98,3707.03 r90 top value=61.9k
R37 "RC0603FR-073K09L" 0603 720.65,3707.03 r270 top value=3.09k
R38 "RC0603FR-075K62L" 0603 503.34,3509.76 r90 top value=5.62k
R39 "CRCW060312K1FKEA" 0603 683.24,3350.54 r90 top value=12.1k
R40 "RC0603FR-0751R1L" 0603 2598,1612.5 r180 top value=51.1
R41 "RC0603FR-0710KL" 0603 1681.16,2428.87 r270 top value=10.0k
R42 "RC0603FR-07300RL" 0603 1880.84,2292.81 r180 top value=300
R43U "RC0603FR-0751R1L" 0603 2597,1216 r180 top value=51.1 (schematic designator R43)
R43V "RC0603FR-0751R1L" 0603 2001,1299 r90 top value=51.1 (schematic designator R43)
R43W "RC0603FR-0751R1L" 0603 2747.45,1381.41 r180 top value=51.1 (schematic designator R43)
R44 "ERJ-2GE0R00X" 0402 3743.03,4407.89 r0 top value=0
R45U "RC0603FR-0722RL" 0603 2746.53,1311.27 r180 top value=22.0 (schematic designator R45)
R45V "RC0603FR-0722RL" 0603 2001,1431.09 r270 top value=22.0 (schematic designator R45)
R45W "RC0603FR-0722RL" 0603 2747.45,1443.92 r180 top value=22.0 (schematic designator R45)
R46 "RC0603FR-0710KL" 0603 1685.04,3158.19 r270 top value=10.0k
R47 "RC0603FR-07300RL" 0603 1880.84,3012.94 r180 top value=300
R48 "RC0603FR-0710KL" 0603 659.59,2019.51 r270 top value=10.0k
R49 "CRCW06030000Z0EBC" FP-CRCW06030000Z0EBC_0603-MFG 631.04,1048.21 r180 top value=0
R50 "RC0603FR-0760R4L" 0603 733.5,912.85 r180 bottom value=60.4
R51 "RC0603FR-0722R1L" 0603 973,830 r180 top value=22.1
R52 "RC0603FR-0760R4L" 0603 733.5,1042 r0 bottom value=60.4
R53 "RC0603FR-0722R1L" 0603 973.24,1048.21 r180 top value=22.1
R54 "CRCW06030000Z0EBC" FP-CRCW06030000Z0EBC_0603-MFG 628.57,838.21 r180 top value=0
R55 "RMCF0603ZT0R00" 0603 807.89,830 r0 top value=0
R56 "ERJ-6ENF1001V" 0805_HV 838.51,1450.59 r90 top value=1.00k
R57 "RC0603FR-0710KL" 0603_HV 956.95,1214.99 r0 top value=10.0k
R58 "RC0603FR-0722R1L" 0603 991.22,1150 r180 top value=22.1
R59 "RC0603FR-0722R1L" 0603 960.45,1300 r180 top value=22.1
R60 "ERJ-6ENF1004V" 0805_HV 617.35,499.94 r180 top value=1.00Meg
R61 "ERJPA2F1002X" 0402 2759.96,3441.2 r270 top value=10.0k
R62 "ERJPA2F1002X" 0402 2711.04,3441.2 r270 top value=10.0k
R63 "ERJPA2F1002X" 0402 2662.42,3441.2 r90 top value=10.0k
R64 "ERJ-2GE0R00X" 0402 2756.81,3017.95 r270 top value=0
R65 "ERJPA2F1002X" 0402 2856.72,2285.44 r270 top value=10.0k
R66 "ERJ-2GE0R00X" 0402 2599.91,2326.94 r180 top value=0
R67 "ERJ-2GE0R00X" 0402 2599.91,2383.87 r180 top value=0
R68 "ERJPA2F1002X" 0402 2929.72,2389.77 r90 top value=10.0k
R69 "ERJPA2F1002X" 0402 2705.72,2477.7 r90 top value=10.0k
R70 "ERJPA2F1002X" 0402 2771.43,2479.08 r90 top value=10.0k
R71 "ERJPA2F1002X" 0402 2878.37,2389.77 r270 top value=10.0k
R72 "ERJPA2F1002X" 0402 2655.12,2477.7 r270 top value=10.0k
R73 "ERJ-2GE0R00X" 0402 2605.9,2477.7 r90 top value=0
R74 "RC0603FR-07300RL" 0603 875.59,1883.22 r180 top value=300
R75 "RC0603FR-0722RL" 0603 2035.5,1621 r0 top value=22.0
R76 "ERJ-3EKF1000V" 0603 2268,519 r180 top value=100
R77 "RC0603FR-074K7L" 0603 2973.55,350.99 r0 top value=4.70k
R78 "RC0603FR-074K7L" 0603 2976.5,252 r180 top value=4.70k
R79 "ERJ-2GE0R00X" 0402 2114,2821.1 r90 top value=0
T1 "750319933" FP-750319933_TRANSFORMER_9MM50_9MM78-MFG 1099.51,3697.38 r0 top
TP1 "5015" Testpoint_Keystone_Miniature 1899.54,1664.1 r90 top
TP2 "5015" Testpoint_Keystone_Miniature 3234.44,3513.9 r0 top
TP3 "5015" Testpoint_Keystone_Miniature 3361.45,513.07 r0 top
TP4U "5015" Testpoint_Keystone_Miniature 5000.1,3226.72 r90 top (schematic designator TP4)
TP4V "5015" Testpoint_Keystone_Miniature 5000.1,1876.72 r90 top (schematic designator TP4)
TP4W "5015" Testpoint_Keystone_Miniature 5000.1,526.72 r90 top (schematic designator TP4)
TP5U "5015" Testpoint_Keystone_Miniature 3789.6,2867.81 r180 top (schematic designator TP5)
TP5V "5015" Testpoint_Keystone_Miniature 3789.6,1517.81 r180 top (schematic designator TP5)
TP5W "5015" Testpoint_Keystone_Miniature 3789.6,167.81 r180 top (schematic designator TP5)
TP6 "SW" Testpoint_Keystone_Miniature 906.61,3403.38 r90 top
TP7 "5015" Testpoint_Keystone_Miniature 655.24,2778.34 r90 top
TP8 "5015" Testpoint_Keystone_Miniature 1521.76,3413.77 r90 top
TP9 "SS/BIAS" Testpoint_Keystone_Miniature 562,3223 r180 top
TP10 "5015" Testpoint_Keystone_Miniature 1528.65,3979.45 r0 top
U1 "OPA607IDBVR" DBV0005A_N 3270.44,3674.07 r90 top
U2 "TLV314QDBVRQ1" DBV0005A_N 3180.47,610.37 r180 top
U3 "LM25184QNGURQ1" NGU0008C 636,3529.13 r270 top
U4U "OPA607IDBVR" DBV0005A_N 3827,3044.95 r90 top (schematic designator U4)
U4V "OPA607IDBVR" DBV0005A_N 3827,1694.95 r90 top (schematic designator U4)
U4W "OPA607IDBVR" DBV0005A_N 3827,344.95 r90 top (schematic designator U4)
U6 "TPS7B6733QPWPRQ1" PWP0020D_N 1861.16,2580.36 r90 top
U7 "TPS7B6750QPWPRQ1" PWP0020D_N 1868.04,3305.69 r90 top
U8 "TPS7B6750QPWPRQ1" PWP0020D_N 845.63,2176.28 r90 top
U9 "TCAN1044DDFRQ1" DDF0008A-MFG 890.57,940.21 r180 top
U10 "ISO6742QDWRQ1" DW0016A-MFG 1321,1050 r180 top
U11 "TLIN1021ADRQ1" D0008A-MFG 745,1225 r180 top
U12 "SN74HC21QPWRG4Q1" PW0014A_N 2739.19,3663.61 r90 top
U13 "TPS3703A4330DSERQ1" DSE0006A 2670.6,3060.8 r0 top
U14 "TPS3850G12QDRCRQ1" DRC0010R 2756.81,2346.47 r180 top
ZZ1 "This Assembly Note is for PCB labels only" AssemblyNoteLabel 447,5706.31 r0 top
ZZ2 "These assemblies are ESD sensitive, ESD precautions shall be observed." AssemblyNote 447,5597.43 r0 top
ZZ3 "These assemblies must be clean and free from flux and all contaminants. Use of no clean flux is not acceptable." AssemblyNote 447,5508.87 r0 top
ZZ4 "These assemblies must comply with workmanship standards IPC-A-610 Class 2, unless otherwise specified." AssemblyNote 447,5420.31 r0 top

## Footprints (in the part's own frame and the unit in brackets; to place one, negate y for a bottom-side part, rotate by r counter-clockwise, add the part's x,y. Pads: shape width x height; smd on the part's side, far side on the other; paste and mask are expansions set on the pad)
0402 [mm] "0402 from SM-752 data"
  rect 0.8x0.6 smd: 1(-0.6,0) 2(0.6,0)
  silkscreen extent -1.22,-0.52 1.22,0.52, body extent -0.55,-0.3 0.55,0.3, height 0.6
0603 [mm] "0603 from SM-752 data"
  rect 1x0.95 smd: 1(-0.8,0) 2(0.8,0)
  silkscreen extent -1.52,-0.69 1.52,0.69, body extent -0.87,-0.47 0.87,0.47, height 1
0603_HV [mil] "Ernesto recommended land pattern.  26 mil between pads."
  rect 30x30 smd: 1(-28,0) 2(28,0)
  silkscreen extent -52,-24 52,24, body extent -34,-19 34,19, height 39
0805_HV [mil] "0805 with 30mil clearance between pads"
  rect 50x63 smd: 1(-40,0) 2(40,0)
  silkscreen extent -74,-40 74,40, body extent -43,-29 43,29, height 57
1206 [mm] "1206 from SM-752 data"
  rect 1.3x1.85 smd: 1(-1.45,0) 2(1.45,0)
  silkscreen extent -2.4,-1.21 2.4,1.21, body extent -1.7,-0.9 1.7,0.9, height 1.35
1206_190M [mm] "1206_190"
  rect 1.5x1.95 smd: 1(-1.55,0) 2(1.55,0)
  silkscreen extent -2.76,-1.44 2.76,1.44, body extent -1.75,-0.95 1.75,0.95, height 1.9
1210_270 [mm] "1210"
  rect 1.3x2.7 smd: 1(-1.45,0) 2(1.45,0)
  silkscreen extent -2.32,-1.57 2.32,1.57, body extent -1.7,-1.35 1.7,1.35, height 2.7
1210_280 [mm] "SMD, 2-Leads, Body 3.6x2.8mm, Height 2.8mm"
  rect 1.1x2.2 smd: 1(-1.65,0) 2(1.65,0)
  silkscreen extent -0.84,-1.4 0.84,1.4, body extent -1.8,-1.4 1.8,1.4, height 2.8
1812 [mm]
  rect 1.6x3.4 smd: 1(-2,0) 2(2,0)
  silkscreen extent -0.8,-1.6 0.8,1.6, body extent -2.4,-1.7 2.4,1.7, height 1.35
ACT45B [mm] "SMD, 4-Leads, Body 4.7 x 3.7 mm"
  rect 1.35x0.9 smd: 1(-2.275,1.25) 2(-2.275,-1.25) 3(2.275,-1.25) 4(2.275,1.25)
  silkscreen extent -2.35,-1.7 2.35,2, body extent -2.35,-1.7 2.35,1.7, height 3
AssemblyNote [mil] "Assembly Note"
AssemblyNoteLabel [mil] "Assembly Note for PCB Labels"
B32776_4200x2800x3700 [mm] "TH, 4-Leads, Body 42x28mm"
  round 2 hole 1.5: 1(-18.75,5.1) 2(-18.75,-5.1) 3(18.75,5.1) 4(18.75,-5.1)
  silkscreen extent -21,-14 21,14, body extent -21,-14 21,14, height 37
CE_Mark_5mm [mil] "Minimum text height for CE Mark"
  silkscreen extent -138,-98 138,98
CONN_SBH11-PBPC-D07-ST-BK [mm] "Sullins recommended land pattern"
  rect 1.65x1.65 hole 1.016 mask+0: 1(-7.62,-1.27)
  round 1.65 hole 1.016 mask+0: 2(-7.62,1.27) 3(-5.08,-1.27) 4(-5.08,1.27) 5(-2.54,-1.27) 6(-2.54,1.27) 7(0,-1.27) 8(0,1.27) 9(2.54,-1.27) 10(2.54,1.27) 11(5.08,-1.27) 12(5.08,1.27) 13(7.62,-1.27) 14(7.62,1.27)
  silkscreen extent -12.64,-5.08 12.64,4.7, body extent -12.64,-4.4 12.64,4.7, height 9.12
controlCARD-120HSEC [mm] "Pads are not numbered according to Samtec datasheet."
  rect 0.5x2.724 smd: 1(-23.357,-1.678) 2(-23.357,1.722) 3(-22.557,-1.678) 4(-22.557,1.722) 5(-21.757,-1.678) 6(-21.757,1.722) 7(-20.957,-1.678) 8(-20.957,1.722) 9(-20.157,-1.678) 10(-20.157,1.722) 11(-19.357,-1.678) 12(-19.357,1.722) 13(-18.557,-1.678) 14(-18.557,1.722) 15(-17.757,-1.678) 16(-17.757,1.722) 17(-16.957,-1.678) 18(-16.957,1.722) 19(-16.157,-1.678) 20(-16.157,1.722) 21(-15.357,-1.678) 22(-15.357,1.722) 23(-14.557,-1.678) 24(-14.557,1.722) 25(-13.757,-1.678) 26(-13.757,1.722) 27(-12.957,-1.678) 28(-12.957,1.722) 29(-12.157,-1.678) 30(-12.157,1.722) 31(-11.357,-1.678) 32(-11.357,1.722) 33(-10.557,-1.678) 34(-10.557,1.722) 35(-9.757,-1.678) 36(-9.757,1.722) 37(-8.957,-1.678) 38(-8.957,1.722) 39(-8.157,-1.678) 40(-8.157,1.722) 41(-7.357,-1.678) 42(-7.357,1.722) 43(-6.557,-1.678) 44(-6.557,1.722) 45(-5.757,-1.678) 46(-5.757,1.722) 47(-4.957,-1.678) 48(-4.957,1.722) 49(-4.157,-1.678) 50(-4.157,1.722) 51(-3.357,-1.678) 52(-3.357,1.722) 53(-2.557,-1.678) 54(-2.557,1.722) 55(-1.757,-1.678) 56(-1.757,1.722) 57(2.243,-1.678) 58(2.243,1.722) 59(3.043,-1.678) 60(3.043,1.722) 61(3.843,-1.678) 62(3.843,1.722) 63(4.643,-1.678) 64(4.643,1.722) 65(5.443,-1.678) 66(5.443,1.722) 67(6.243,-1.678) 68(6.243,1.722) 69(7.043,-1.678) 70(7.043,1.722) 71(7.843,-1.678) 72(7.843,1.722) 73(8.643,-1.678) 74(8.643,1.722) 75(9.443,-1.678) 76(9.443,1.722) 77(10.243,-1.678) 78(10.243,1.722) 79(11.043,-1.678) 80(11.043,1.722) 81(11.843,-1.678) 82(11.843,1.722) 83(12.643,-1.678) 84(12.643,1.722) 85(13.443,-1.678) 86(13.443,1.722) 87(14.243,-1.678) 88(14.243,1.722) 89(15.043,-1.678) 90(15.043,1.722) 91(15.843,-1.678) 92(15.843,1.722) 93(16.643,-1.678) 94(16.643,1.722) 95(17.443,-1.678) 96(17.443,1.722) 97(18.243,-1.678) 98(18.243,1.722) 99(19.043,-1.678) 100(19.043,1.722) 101(19.843,-1.678) 102(19.843,1.722) 103(20.643,-1.678) 104(20.643,1.722) 105(21.443,-1.678) 106(21.443,1.722) 107(22.243,-1.678) 108(22.243,1.722) 109(23.043,-1.678) 110(23.043,1.722) 111(23.843,-1.678) 112(23.843,1.722) 113(24.643,-1.678) 114(24.643,1.722) 115(25.443,-1.678) 116(25.443,1.722) 117(26.243,-1.678) 118(26.243,1.722) 119(27.043,-1.678) 120(27.043,1.722)
  round 0.025 hole 1.27 unplated mask+0.876: 181(-24.857,0.022) 182(28.543,1.522)
  round 1.348 hole 0.84: 185(-27.207,0.022) 186(30.893,0.022)
  silkscreen extent -32.11,-3.86 35.8,3.9, body extent -31.75,-3.48 35.3,3.52, height 12.35
controlCARD-180HSEC-60pinAddon [mm] "Pads are not numbered according to datasheet."
  round 0.025 hole 1.27 unplated mask+0.876: 61(-13.1,0) 62(13.1,1.5)
  rect 0.5x2.724 smd: 121(-11.6,-1.7) 122(-11.6,1.7) 123(-10.8,-1.7) 124(-10.8,1.7) 125(-10,-1.7) 126(-10,1.7) 127(-9.2,-1.7) 128(-9.2,1.7) 129(-8.4,-1.7) 130(-8.4,1.7) 131(-7.6,-1.7) 132(-7.6,1.7) 133(-6.8,-1.7) 134(-6.8,1.7) 135(-6,-1.7) 136(-6,1.7) 137(-5.2,-1.7) 138(-5.2,1.7) 139(-4.4,-1.7) 140(-4.4,1.7) 141(-3.6,-1.7) 142(-3.6,1.7) 143(-2.8,-1.7) 144(-2.8,1.7) 145(-2,-1.7) 146(-2,1.7) 147(-1.2,-1.7) 148(-1.2,1.7) 149(-0.4,-1.7) 150(-0.4,1.7) 151(0.4,-1.7) 152(0.4,1.7) 153(1.2,-1.7) 154(1.2,1.7) 155(2,-1.7) 156(2,1.7) 157(2.8,-1.7) 158(2.8,1.7) 159(3.6,-1.7) 160(3.6,1.7) 161(4.4,-1.7) 162(4.4,1.7) 163(5.2,-1.7) 164(5.2,1.7) 165(6,-1.7) 166(6,1.7) 167(6.8,-1.7) 168(6.8,1.7) 169(7.6,-1.7) 170(7.6,1.7) 171(8.4,-1.7) 172(8.4,1.7) 173(9.2,-1.7) 174(9.2,1.7) 175(10,-1.7) 176(10,1.7) 177(10.8,-1.7) 178(10.8,1.7) 179(11.6,-1.7) 180(11.6,1.7)
  silkscreen extent -14.68,-3.88 14.68,3.88, body extent -14.3,-3.5 14.3,3.5, height 7.95
D0008A-MFG [mm]
  rrect17% 1.55x0.6 smd paste+0 mask+0: 1(-2.7,1.905) 2(-2.7,0.635) 3(-2.7,-0.635) 4(-2.7,-1.905) 5(2.7,-1.905) 6(2.7,-0.635) 7(2.7,0.635) 8(2.7,1.905)
  silkscreen extent -4.18,-2.5 1.5,2.5, body extent -3.57,-2.75 3.57,2.75, height 0.25
DBV0005A_N [mm] "SOT23, 5-Leads, Body 2.9x1.6mm, Pitch 0.95mm, Lead Span 2.8mm, IPC Medium Density"
  rrect17% 1x0.6 smd: 1(-1.375,0.95) 2(-1.375,0) 3(-1.375,-0.95) 4(1.375,-0.95) 5(1.375,0.95)
  silkscreen extent -1.63,-1.55 0.38,1.55, body extent -1.42,-1.46 1.42,1.46, height 1.09
DDF0008A-MFG [mm]
  rrect22% 1.05x0.45 smd paste+0 mask+0: 1(-1.3,0.975) 2(-1.3,0.325) 3(-1.3,-0.325) 4(-1.3,-0.975) 5(1.3,-0.975) 6(1.3,-0.325) 7(1.3,0.325) 8(1.3,0.975)
  silkscreen extent -2.5,-1.48 0.4,1.48, body extent -1.92,-1.73 1.92,1.73, height 0.25
DRC0010R [mm] "VSON-10"
  rrect40% 0.6x0.25 smd: 1(-1.4,1) 2(-1.4,0.5) 3(-1.4,0) 4(-1.4,-0.5) 5(-1.4,-1) 6(1.4,-1) 7(1.4,-0.5) 8(1.4,0) 9(1.4,0.5) 10(1.4,1)
  rrect12% 1.65x2.4 smd paste-1 mask-2: 11(0,0)
  Top Layer region: -0.375,-1.65 -0.375,-1.2 -0.775,-1.2 -0.794,-1.196 -0.81,-1.185 -0.821,-1.169 -0.825,-1.15 -0.825,-1.15 -0.825,1.15 -0.821,1.169 -0.81,1.185 -0.794,1.196 -0.775,1.2 -0.775,1.2 -0.375,1.2 -0.375,1.65 -0.371,1.669 -0.36,1.685 -0.344,1.696 -0.325,1.7 -0.325,1.7 -0.325,1.7 -0.175,1.7 -0.175,1.7 -0.156,1.696 -0.14,1.685 -0.129,1.669 -0.125,1.65 -0.125,1.65 -0.125,1.2 0.125,1.2 0.125,1.65 0.129,1.669 0.14,1.685 0.156,1.696 0.175,1.7 0.175,1.7 0.175,1.7 0.325,1.7 0.325,1.7 0.344,1.696 0.36,1.685 0.371,1.669 0.375,1.65 0.375,1.65 0.375,1.2 0.775,1.2 0.794,1.196 0.81,1.185 0.821,1.169 0.825,1.15 0.825,1.15 0.825,-1.15 0.821,-1.169 0.81,-1.185 0.794,-1.196 0.775,-1.2 0.775,-1.2 0.375,-1.2 0.375,-1.65 0.371,-1.669 0.36,-1.685 0.344,-1.696 0.325,-1.7 0.325,-1.7 0.175,-1.7 0.156,-1.696 0.14,-1.685 0.129,-1.669 0.125,-1.65 0.125,-1.65 0.125,-1.2 -0.125,-1.2 -0.125,-1.65 -0.129,-1.669 -0.14,-1.685 -0.156,-1.696 -0.175,-1.7 -0.175,-1.7 -0.325,-1.7 -0.344,-1.696 -0.36,-1.685 -0.371,-1.669 -0.375,-1.65
  silkscreen extent -1.65,-1.65 1.65,1.65, body extent -1.5,-1.5 1.5,1.5, height 0.87
DSE0006A [mm] "TI recommended land pattern"
  rect 0.66x0.25 smd: 1(-0.62,0.5)
  rect 0.7x0.25 smd: 2(-0.6,0) 3(-0.6,-0.5) 4(0.6,-0.5) 5(0.6,0) 6(0.6,0.5)
  Top Layer region: -0.3,0.625 -0.25,0.625 -0.15,0.525 -0.15,0.375 -0.3,0.375
  silkscreen extent -0.9,-0.92 0.9,0.92, body extent -0.77,-0.77 0.77,0.77, height 0.8
DW0016A-MFG [mm]
  rrect17% 2x0.6 smd paste+0 mask+0: 1(-4.65,4.445) 2(-4.65,3.175) 3(-4.65,1.905) 4(-4.65,0.635) 5(-4.65,-0.635) 6(-4.65,-1.905) 7(-4.65,-3.175) 8(-4.65,-4.445) 9(4.65,-4.445) 10(4.65,-3.175) 11(4.65,-1.905) 12(4.65,-0.635) 13(4.65,0.635) 14(4.65,1.905) 15(4.65,3.175) 16(4.65,4.445)
  silkscreen extent -6.33,-5.25 3.15,5.25, body extent -5.75,-5.35 5.75,5.35, height 0.25
FCC_disclaimer [mil]
FP-750319933_TRANSFORMER_9MM50_9MM78-MFG [mm]
  rrect9% 1.91x1.17 smd paste+0 mask+0: 1(-4.065,-3.75) 2(-4.065,-1.25) 3(-4.065,1.25) 4(-4.065,3.75) 5(4.065,3.75) 6(4.065,1.25) 7(4.065,-1.25) 8(4.065,-3.75)
  silkscreen extent -5.82,-4.89 4.75,4.89, body extent -5.12,-4.99 5.12,4.99, height 0.25
FP-CRCW06030000Z0EBC_0603-MFG [mm]
  rrect20% 0.5x0.9 smd paste+0 mask+0: 1(-0.75,0) 2(0.75,0)
  silkscreen extent -0.13,-0.45 0.13,0.45, body extent -1.1,-0.55 1.1,0.55, height 0.25
IEC_HighVoltage_Medium [mil]
  silkscreen extent -217,-176 217,200
Keystone_1902C [mil] "Hex Standoff, 4-40 threaded, nylon"
  round 1 on Mech4: 0(0,0)
  body extent -145,-126 146,126, height 501
Label_650x200 [mil] "Thermal Transfer Label"
  round 1 on Mech13: 0(0,0)
  silkscreen extent -325,-100 325,100, body extent -325,-100 325,100, height 1
LPG0002A-MFG [mm]
  rrect9% 1.07x1.7 hole 0.75 paste-1000 mask+0: 1(-1.27,0.21)
  rrect100% 1.07x1.7 hole 0.75 paste-1000 mask+0: 2(1.27,0.21)
  round 0.75 hole 0.75 unplated paste-1000 mask+0: ""(0,0.21)
  silkscreen extent -2.8,-0.81 2.2,0.81, body extent -2,-0.76 2,0.76, height 5.25
Mill-Max_0312-0-15-15-34-27-10-0 [mm] "Pin Receptacle, .032-.046\" .075\" Dia, Gold, TH"
  round 2.45 hole 1.905: 1(0,0)
  silkscreen extent -1.52,-1.52 1.52,1.52, body extent -1.15,-1.15 1.16,1.15, height 0.46
Net-Tie_10milWide_30milLong [mil] "10mil net tie, no solder mask opening, no solder paste"
  rect 30x10 smd paste-5 mask-5: 1(-15,0) 2(15,0)
NGU0008C [mm] "SON, 8-Leads, Body 4x4mm, Pitch 0.8mm"
  rrect33% 0.6x0.3 smd: 1(-1.9,1.2) 2(-1.9,0.4) 3(-1.9,-0.4) 4(-1.9,-1.2) 5(1.9,-1.2) 6(1.9,-0.4) 7(1.9,0.4) 8(1.9,1.2)
  rrect8% 1.75x1.31 on Top Paste: 9(0,0.755) 9(0,-0.755)
  rrect5% 1.98x3 smd paste-1.5: 9(0,0)
  silkscreen extent -2.15,-2.15 2.15,2.15, body extent -2,-2 2,2, height 0.77
"NY PMS 440 0025 PH" [mm] "4-40 nylon screw and mounting hole"
  round 8 hole 5.08: 1(0,0)
  body extent -3.3,-3.3 3.3,3.3, height 2.69
PW0014A_N [mm] "TSOP, 14-Leads, Body 5x4.4mm, Pitch 0.65mm, IPC Medium Density"
  oval 1.4x0.45 smd: 1(-2.95,1.95) 2(-2.95,1.3) 3(-2.95,0.65) 4(-2.95,0) 5(-2.95,-0.65) 6(-2.95,-1.3) 7(-2.95,-1.95) 8(2.95,-1.95) 9(2.95,-1.3) 10(2.95,-0.65) 11(2.95,0) 12(2.95,0.65) 13(2.95,1.3) 14(2.95,1.95)
  silkscreen extent -3.4,-2.55 1.85,2.55, body extent -3.21,-2.5 3.21,2.5, height 1
PWP0020D_N [mm] "HTSSOP-20, IPC Medium Density"
  rrect22% 1.4x0.45 smd: 1(-2.95,2.925) 2(-2.95,2.275) 3(-2.95,1.625) 4(-2.95,0.975) 5(-2.95,0.325) 6(-2.95,-0.325) 7(-2.95,-0.975) 8(-2.95,-1.625) 9(-2.95,-2.275) 10(-2.95,-2.925) 11(2.95,-2.925) 12(2.95,-2.275) 13(2.95,-1.625) 14(2.95,-0.975) 15(2.95,-0.325) 16(2.95,0.325) 17(2.95,0.975) 18(2.95,1.625) 19(2.95,2.275) 20(2.95,2.925)
  rrect6% 3.4x6.5 smd paste-2 mask-2: 21(0,0)
  silkscreen extent -3.55,-3.3 1.5,3.4, body extent -3.2,-3.25 3.2,3.25, height 1.13
SMA [mm] "Molded Diode, 2-Leads, Body 4.3x2.6mm, IPC Medium Density, based on OnSemi component dimensions and land pattern"
  rect 2x2 smd: 1(-2,0) 2(2,0)
  silkscreen extent -3.66,-1.57 2.79,1.57, body extent -2.6,-1.3 2.6,1.3, height 2.42
SMC_265 [mm] "SMD, 2-Leads, Body 7.15x6.25mm"
  rect 2.6x3.2 smd: 1(-3.6,0) 2(3.6,0)
  silkscreen extent -5.6,-3.23 5.3,3.22, body extent -4.07,-3.13 4.07,3.13, height 2.65
SOD-123 [mm] "On Semi recommended land pattern"
  rect 0.915x1.22 smd: 1(-1.637,0) 2(1.637,0)
  silkscreen extent -2.74,-1.17 2.03,1.17, body extent -1.93,-0.9 1.93,0.9, height 1.35
SOD-123HE [mm] "SMD, 2-Leads, Body 2.8x1.8mm"
  rect 2.3x1.4 smd: 1(-0.9,0)
  rect 1.25x1.4 smd: 2(1.425,0)
  silkscreen extent -2.7,-1.1 2,1.1, body extent -1.5,-0.97 1.5,0.97, height 1
SOD-123W [mm] "NXP recommended land pattern"
  rect 1.2x1.2 smd paste-0.05: 1(-1.4,0) 2(1.4,0)
  silkscreen extent -2.64,-1.14 1.68,1.14, body extent -1.85,-0.95 1.85,0.95, height 1.1
SOD-323 [mm] "NXP recommended land pattern"
  rect 0.6x0.6 smd paste-0.05: 1(-1.1,0) 2(1.1,0)
  silkscreen extent -2.06,-0.86 1.53,0.86, body extent -1.3,-0.67 1.3,0.68, height 1.1
SOD-323-Bi [mm] "SOD323, 2-Leads, Body 1.9x1.45mm, No Polarity Mark"
  rect 0.6x0.6 smd paste-0.05: 1(-1.1,0) 2(1.1,0)
  silkscreen extent -1.53,-0.77 1.53,0.77, body extent -1.27,-0.65 1.27,0.65, height 1.02
SOD-523 [mm] "NXP Semiconductor recommended land pattern, nominal STEP model"
  rect 0.8x0.6 smd paste-0.05: 1(-0.55,0) 2(0.55,0)
  silkscreen extent -1.65,-0.66 1.2,0.66, body extent -0.8,-0.4 0.8,0.4, height 0.72
SOT-23 [mm] "SOT23, 3-Leads, Body 2.9x1.3mm, Pitch 0.95mm, Lead Span 2.5mm, IPC Medium Density"
  rrect50% 1x0.6 smd: 1(-1.2,0.95) 2(-1.2,-0.95) 3(1.2,0)
  silkscreen extent -1.62,-1.5 0.7,1.5, body extent -1.16,-1.45 1.21,1.45, height 1
TE_215307-3 [mm] "Receptacle, 2.54mm, 3x2, TH"
  rrect50% 1.35x1.35 hole 0.9: 1(-2.54,1.27)
  round 1.35 hole 0.9: 2(-2.54,-1.27) 3(0,1.27) 4(0,-1.27) 5(2.54,1.27) 6(2.54,-1.27)
  body extent -3.81,-2.53 3.81,2.53, height 7
Testpoint_Keystone_Miniature [mil] "Miniature SMT test point"
  rect 135x70 smd: 1(0,0)
  silkscreen extent -78,-46 78,45, body extent -52,-20 52,20, height 61
TI_Stacked_Overlay_Small [mil]
  silkscreen extent -418,-98 418,98
TO-247_Horizontal_Down [mil] "TH, 3-Leads, Body 16.13x 21.1mm, Pitch 5.461mm"
  rrect50% 95x95 / inner round 78 / far side rrect50% 95x95 hole 62: 1(-215,0)
  round 95 / inner round 78 / far side round 95 hole 62: 2(0,0) 3(215,0)
  round 141.73 hole 141.73 unplated: MH-1(0,-822.83)
  silkscreen extent -346,-1067 318,-60, body extent -318,-1067 318,13, height 400
TSW-102-07-G-S [mm] "Samtec 100mil, 1x2, 230 mil above insulator"
  rrect50% 1.65x1.65 hole 1.016: 1(-1.27,0)
  round 1.65 hole 1.016: 2(1.27,0)
  silkscreen extent -3.17,-1.27 2.54,1.27, body extent -2.54,-1.27 2.54,1.27, height 8.38
WEEE_Minimum [mil] "WEEElie bin"
  silkscreen extent -95,-172 99,104
WL-SMCW_YELLOW [mm] "WURTH"
  rect 0.8x0.8 smd: 1(-0.8,0) 2(0.8,0)
  silkscreen extent -1.9,-0.8 1.2,0.8, body extent -0.85,-0.45 0.85,0.45, height 0.8
Wurth_618009231121 [mm] "Receptacle, D-Sub, 9 Position, R/A, TH"
  rect 1.5x1.5 hole 1: 1(-10.92,5.54)
  round 1.5 hole 1: 2(-10.92,2.77) 3(-10.92,0) 4(-10.92,-2.77) 5(-10.92,-5.54) 6(-8.08,4.155) 7(-8.08,1.385) 8(-8.08,-1.385) 9(-8.08,-4.155)
  round 3.7 hole 3.2: 10(-9.5,12.5) 11(-9.5,-12.5)
  silkscreen extent -12.78,-15.4 -0.53,15.4, body extent -12.5,-15.4 6,15.4, height 12.5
